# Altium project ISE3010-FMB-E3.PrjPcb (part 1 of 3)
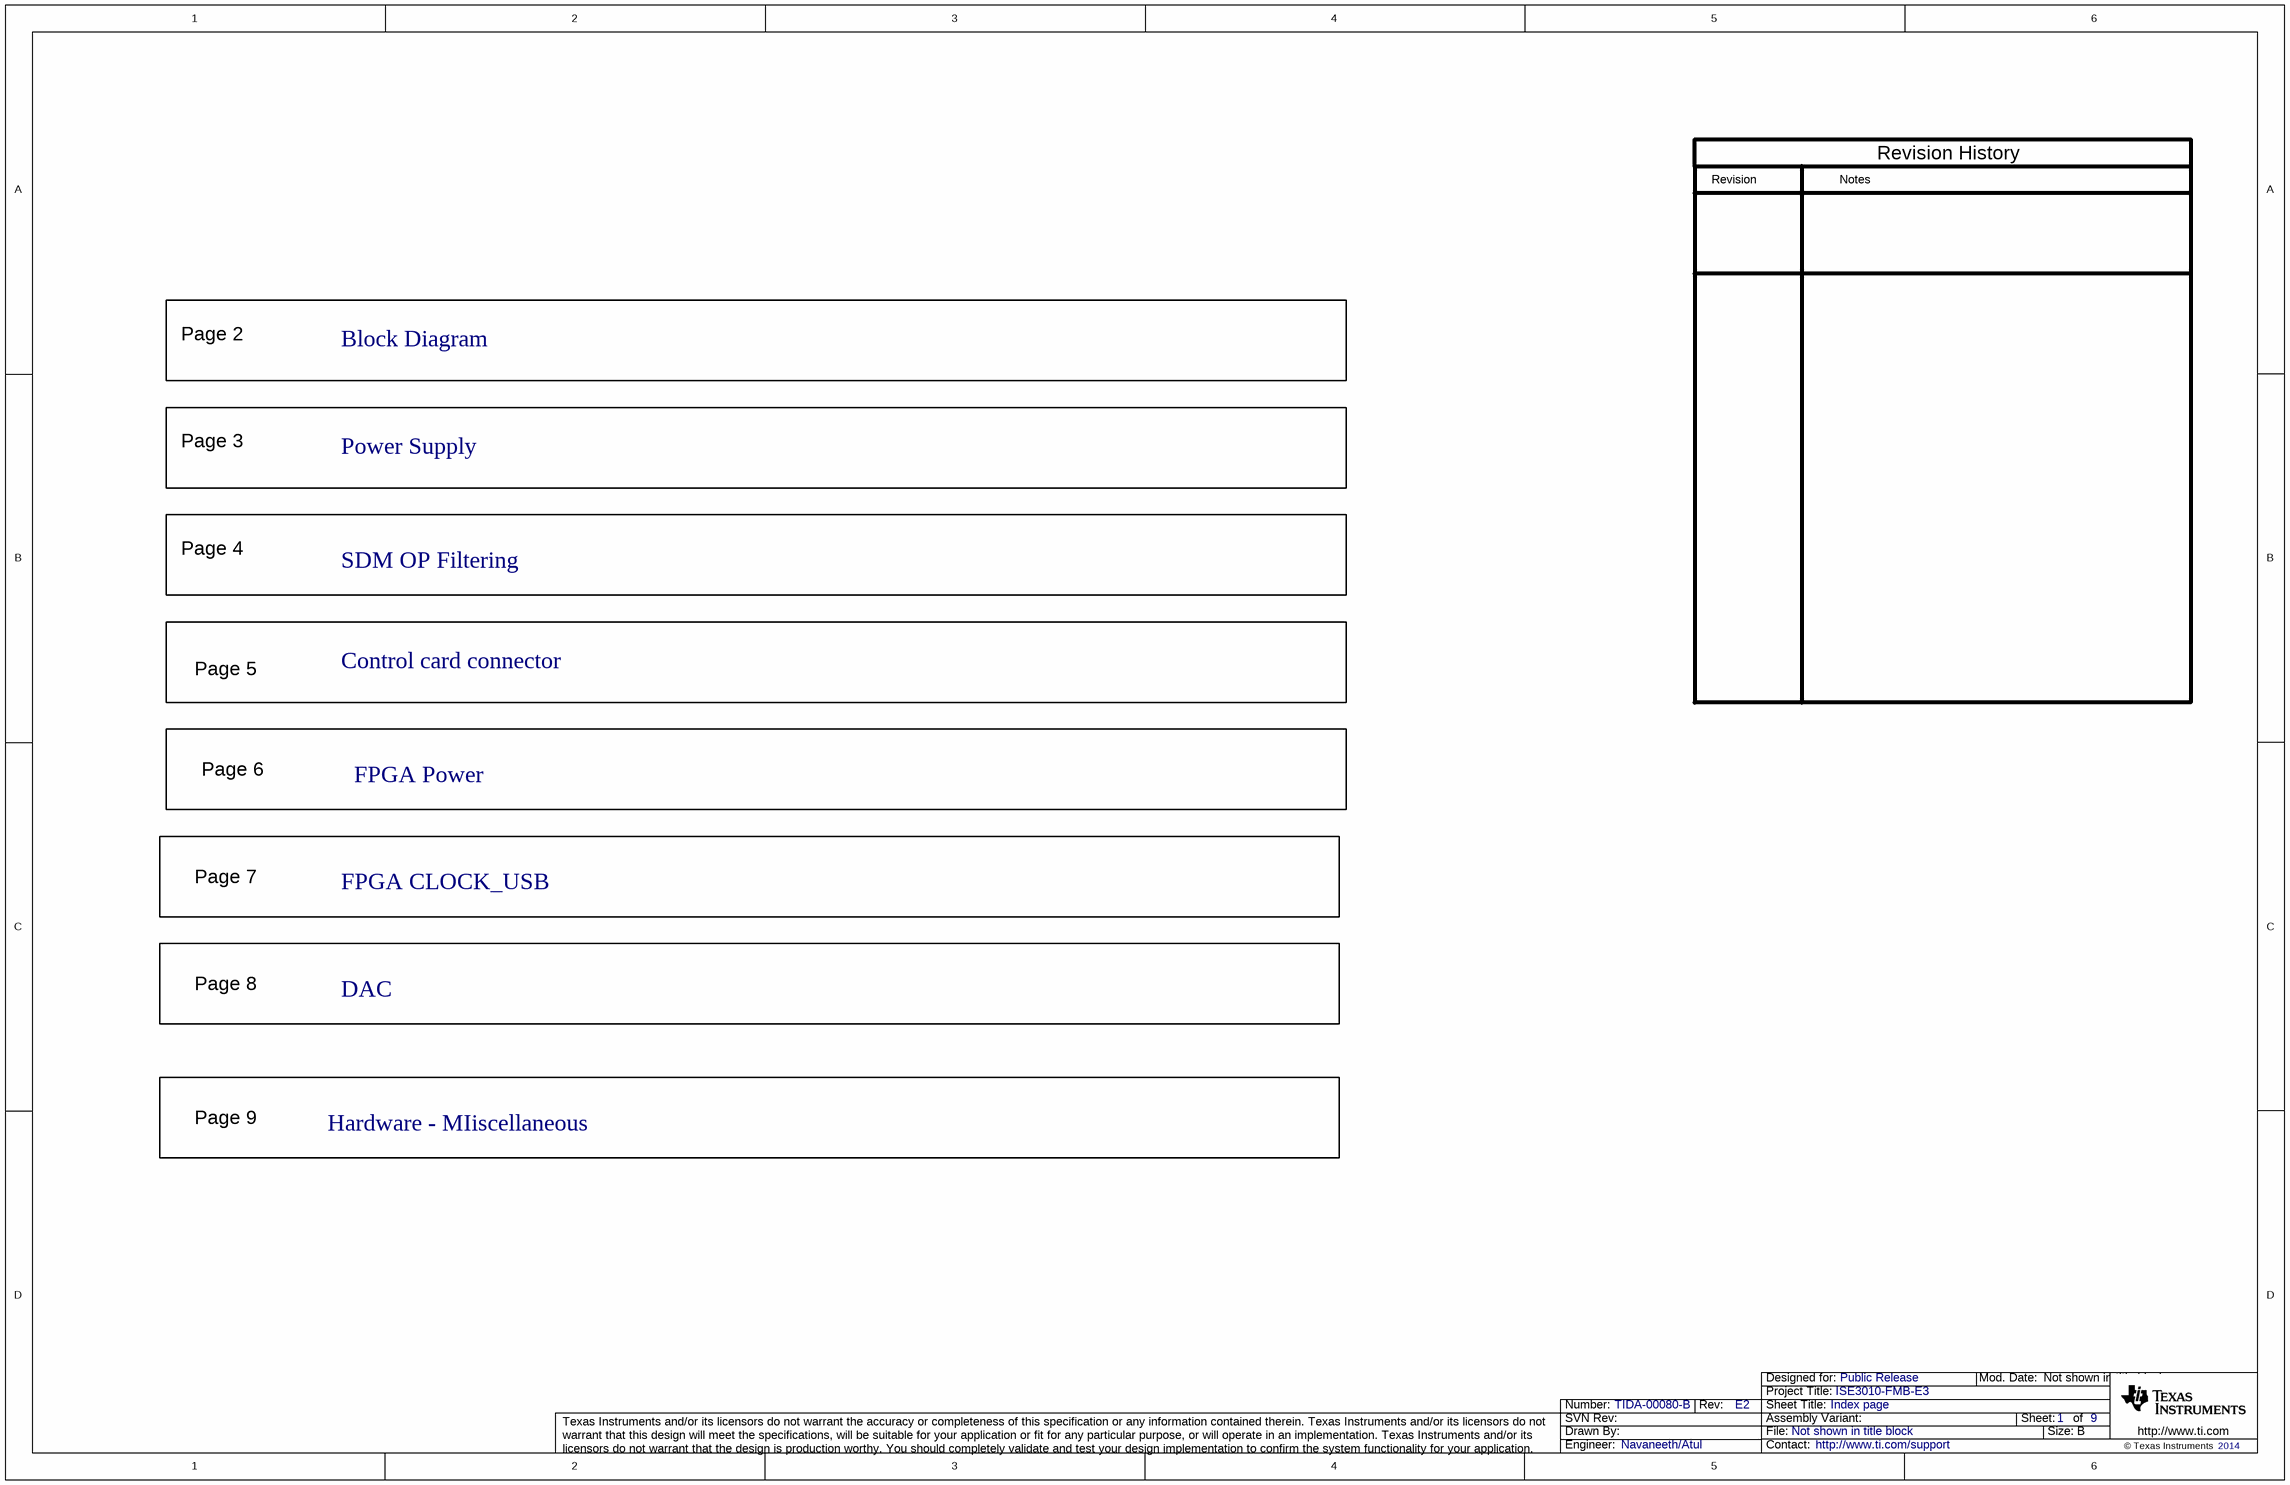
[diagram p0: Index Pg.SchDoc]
CopyrightYear: 2014; PCB_Rev: E2; PRJ_Customer: Public Release; PRJ_Engineer: Navaneeth/Atul; PRJ_Number: TIDA-00080-B; PRJ_Title: ISE3010-FMB-E3; SCH_Rev: E2; TechSupport: http://www.ti.com/support
9 sheets, 508 parts. Net scope: flat (ports and power ports of the same name join across sheets).
Board file: ISE3010-FMB-E3.PcbDoc
Sheets:
  Index Pg.SchDoc
  Block Diagram.SchDoc
  Power Supply.SchDoc
  SDM OP Filtering.SchDoc
  Control card connector.SchDoc
  FPGA Power.SchDoc
  FPGA CLOCK_USB.SchDoc
  DAC.SchDoc
  Hardware.SchDoc

## Sheet Index Pg.SchDoc: Index page
size 431 x 279 mm; Date: Not shown in title block; ApprovedBy: Not shown in title block; CheckedBy: Not shown in title block; Author: Not shown in title block; CompanyName: Not shown in title block; Engineer: Not shown in title block; Organization: Not shown in title block; Address1: Not shown in title block; Address2: Not shown in title block; Address3: Not shown in title block; Address4: Not shown in title block; DocumentNumber: 1; Revision: Use project parameter SCH_Rev; SheetNumber: 1; SheetTotal: 9; PageSetup: Record=PageOptions|CenterHorizontal=True|CenterVertical=True|PrintScale=0.64|XCorrection=1.00|YCorrection=1.00|PrintKind=0|BorderSize=5000000|LeftOffset=0|BottomOffset=0|Orientation=2|PaperLength=1000|PaperWidth=1000|Scale=100|PaperSource=15|PrintQuality=600|MediaType=1|DitherType=10|PaperKind=Letter|PrintScaleMode=1

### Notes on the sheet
- Revision History
- Revision
- Notes
- Page 2
- Block Diagram
- Page 3
- Power Supply
- Page 4
- SDM OP Filtering
- Page 5
- Control card connector
- Page 6
- FPGA Power
- Page 7
- FPGA CLOCK_USB
- Page 8
- DAC
- Page 9
- Hardware - MIiscellaneous

## Sheet Block Diagram.SchDoc: Block Diagram
size 431 x 279 mm; Date: Not shown in title block; ApprovedBy: Not shown in title block; CheckedBy: Not shown in title block; Author: Not shown in title block; CompanyName: Not shown in title block; Engineer: Not shown in title block; Organization: Not shown in title block; Address1: Not shown in title block; Address2: Not shown in title block; Address3: Not shown in title block; Address4: Not shown in title block; DocumentNumber: 2; Revision: Use project parameter SCH_Rev; SheetNumber: 2; SheetTotal: 9; PageSetup: Record=PageOptions|CenterHorizontal=True|CenterVertical=True|PrintScale=1.00|XCorrection=1.00|YCorrection=1.00|PrintKind=0|BorderSize=5000000|LeftOffset=0|BottomOffset=0|Orientation=2|PaperLength=1000|PaperWidth=1000|Scale=100|PaperSource=15|PrintQuality=600|MediaType=1|DitherType=10|PaperKind=Letter|PrintScaleMode=1
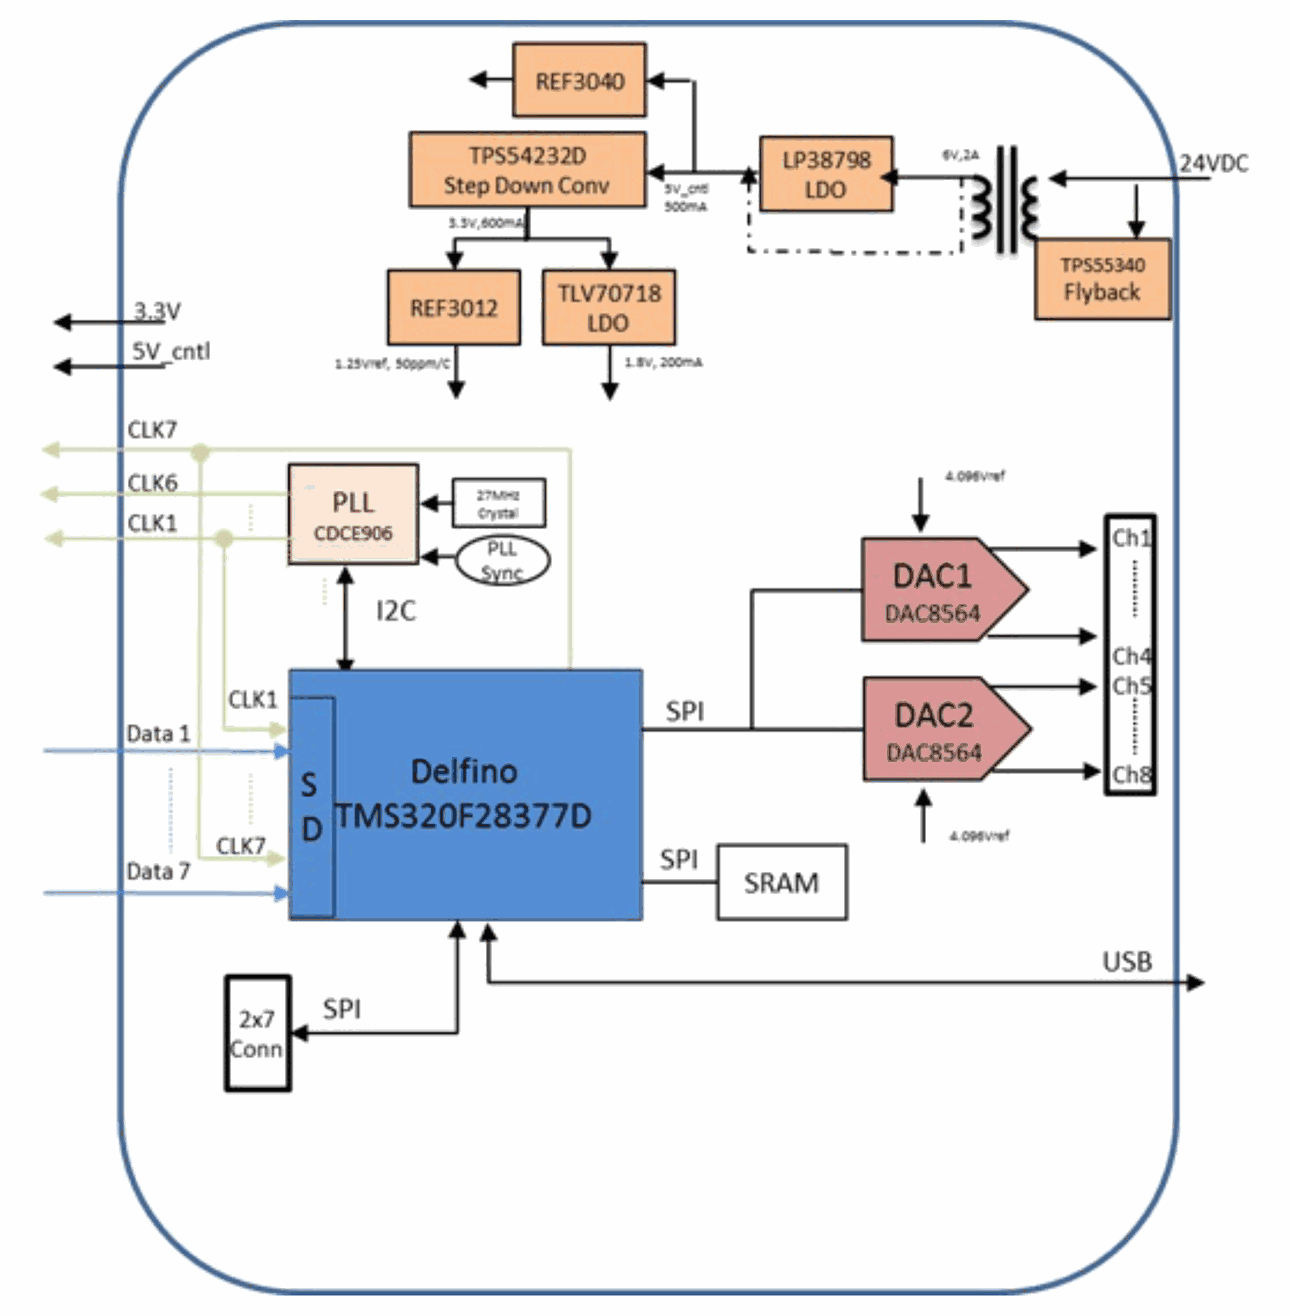
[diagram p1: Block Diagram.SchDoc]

## Sheet Power Supply.SchDoc: Power Supply
size 431 x 279 mm; Date: Not shown in title block; ApprovedBy: Not shown in title block; CheckedBy: Not shown in title block; Author: Not shown in title block; CompanyName: Not shown in title block; Engineer: Not shown in title block; Organization: Not shown in title block; Address1: Not shown in title block; Address2: Not shown in title block; Address3: Not shown in title block; Address4: Not shown in title block; DocumentNumber: 3; Revision: Use project parameter SCH_Rev; SheetNumber: 3; SheetTotal: 9; PageSetup: Record=PageOptions|CenterHorizontal=True|CenterVertical=True|PrintScale=1.00|XCorrection=1.00|YCorrection=1.00|PrintKind=0|BorderSize=5000000|LeftOffset=0|BottomOffset=0|Orientation=2|PaperLength=1000|PaperWidth=1000|Scale=100|PaperSource=15|PrintQuality=600|MediaType=1|DitherType=10|PaperKind=Letter|PrintScaleMode=1
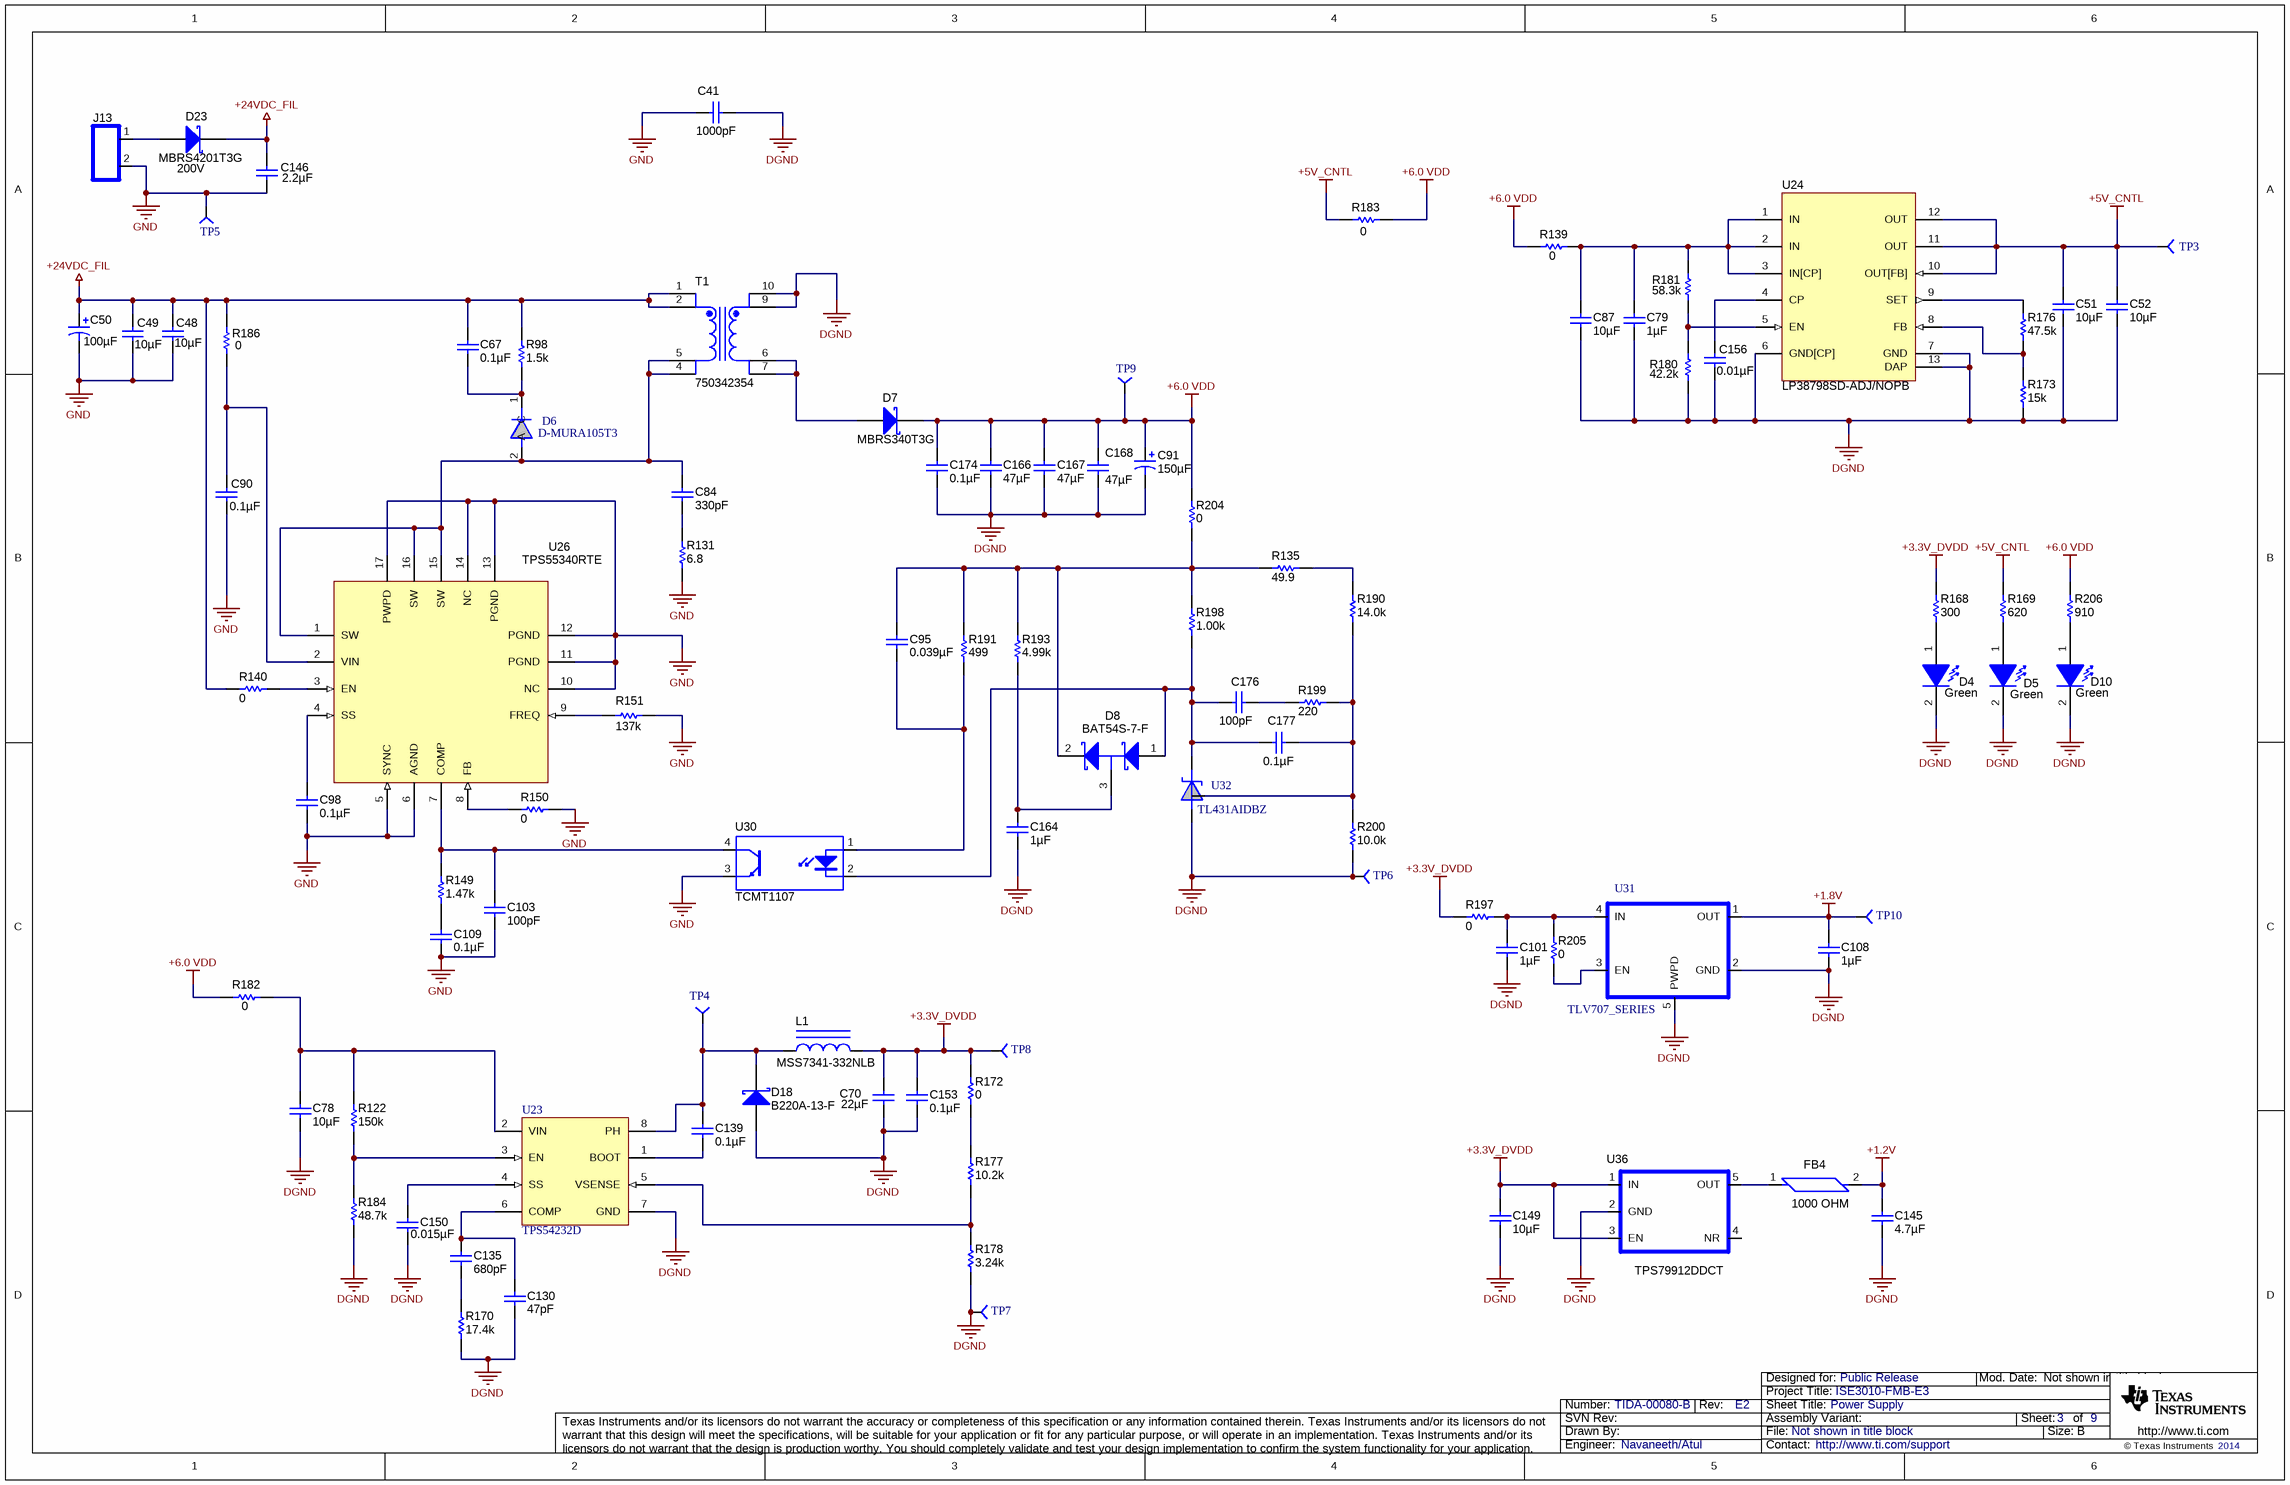
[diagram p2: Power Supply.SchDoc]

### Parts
C41  value 1000pF  [1206]
C48  ValueDisplayed: 10µF  [1210]  (hidden comment: GRM32ER71H106KA12L)
C49  ValueDisplayed: 10µF  [1210]  (hidden comment: GRM32ER71H106KA12L)
C50  ValueDisplayed: 100µF  [HE_800x1150]  (hidden comment: UHE1H101MPD)
C51  ValueDisplayed: 10µF  [1206]  (hidden comment: GRM31CR71C106KAC7L)
C52  ValueDisplayed: 10µF  [1206]  (hidden comment: GRM31CR71C106KAC7L)
C67  ValueDisplayed: 0.1µF  [0603]  (hidden comment: C0603C104K5RACTU)
C70  ValueDisplayed: 22µF  [1210]  (hidden comment: C3225X5R1A226M)
C78  ValueDisplayed: 10µF  [1206]  (hidden comment: GMK316AB7106KL)
C79  ValueDisplayed: 1µF  [1206]  (hidden comment: 12063C105KAT2A)
C84  ValueDisplayed: 330pF  [0603]  (hidden comment: 06035A331JAT2A)
C87  ValueDisplayed: 10µF  [1206]  (hidden comment: GRM31CR71C106KAC7L)
C90  ValueDisplayed: 0.1µF  [0603]  (hidden comment: C0603C104K5RACTU)
C91  ValueDisplayed: 150µF  [SM_RADIAL_6.3BMM]  (hidden comment: UUD1C151MCL1GS)
C95  ValueDisplayed: 0.039µF  [0603]  (hidden comment: GRM188R71H393KA61D)
C98  ValueDisplayed: 0.1µF  [0603]  (hidden comment: 06035C104KAT2A)
C101  ValueDisplayed: 1µF  [0603]  (hidden comment: GRM188R71A105KA61D)
C103  ValueDisplayed: 100pF  [0603]  (hidden comment: C1608C0G1H101J)
C108  ValueDisplayed: 1µF  [0603]  (hidden comment: GRM188R71A105KA61D)
C109  ValueDisplayed: 0.1µF  [0603]  (hidden comment: C0603C104K5RACTU)
C130  ValueDisplayed: 47pF  [0402]  (hidden comment: GRM1555C1E470JA01D)
C135  ValueDisplayed: 680pF  [0603]  (hidden comment: GRM1885C1E681JA01D)
C139  ValueDisplayed: 0.1µF  [0603]  (hidden comment: 0603YC104JAT2A)
C145  ValueDisplayed: 4.7µF  [0603]  (hidden comment: C0603C475K9PACTU)
C146  ValueDisplayed: 2.2µF  [1210]
C149  ValueDisplayed: 10µF  [1210]
C150  ValueDisplayed: 0.015µF  [0603]  (hidden comment: GRM188R71C153KA01D)
C153  ValueDisplayed: 0.1µF  [0603]  (hidden comment: C0603X104K8RACTU)
C156  ValueDisplayed: 0.01µF  [0805_HV]  (hidden comment: 08055C103KAT2A)
C164  ValueDisplayed: 1µF  [0603]  (hidden comment: C0603C105K4PACTU)
C166  ValueDisplayed: 47µF  [1210]  (hidden comment: GRM32ER61A476KE20L)
C167  ValueDisplayed: 47µF  [1210]  (hidden comment: GRM32ER61A476KE20L)
C168  ValueDisplayed: 47µF  [1210]  (hidden comment: GRM32ER61A476KE20L)
C174  ValueDisplayed: 0.1µF  [0603]  (hidden comment: C0603X104K8RACTU)
C176  ValueDisplayed: 100pF  [0603]  (hidden comment: C1608C0G1H101J)
C177  ValueDisplayed: 0.1µF  [0603]  (hidden comment: C0603C104K5RACTU)
D4  value Green  [LED_0603]  (hidden comment: LG L29K-G2J1-24-Z)
D5  value Green  [LED_0603]  (hidden comment: LG L29K-G2J1-24-Z)
D6  D-MURA105T3  [403D]
D7  MBRS340T3G  [SMC]
D8  BAT54S-7-F  [SOT-23]
D10  value Green  [LED_0603]  (hidden comment: LG L29K-G2J1-24-Z)
D18  B220A-13-F  [SMA]
D23  value 200V  [SMC]  (hidden comment: MBRS4201T3G)
FB4  value 1000 OHM  [FB0603]
J13  TBLK_15A_2X5.1MM  [TB_2X5.1MM]  (value not drawn)
L1  MSS7341-332NLB  [MSS7341]
R98  value 1.5k  [1206]  (hidden comment: CRCW12061K50JNEA)
R122  value 150k  [0603]  (hidden comment: RC0603FR-07150KL)
R131  value 6.8  [1206]  (hidden comment: CRCW12066R80JNEA)
R135  value 49.9  [0603]  (hidden comment: CRCW060349R9FKEA)
R139  value 0  [0603]  (hidden comment: CRCW06030000Z0EA)
R140  value 0  [0603]  (hidden comment: CRCW06030000Z0EA)
R149  value 1.47k  [0603]  (hidden comment: RC0603FR-071K47L)
R150  value 0  [0603]  (hidden comment: CRCW06030000Z0EA)
R151  value 137k  [0603]  (hidden comment: CRCW0603137KFKEA)
R168  value 300  [0603]  (hidden comment: CRCW0603300RJNEA)
R169  value 620  [0603]  (hidden comment: RC0603FR-07620RL)
R170  value 17.4k  [0603]  (hidden comment: CRCW060317K4FKEA)
R172  value 0  [0603]  (hidden comment: RC0603JR-070RL)
R173  value 15k  [0603]  (hidden comment: CRCW060315K0JNEA)
R176  value 47.5k  [0603]  (hidden comment: CRCW060347K5FKEA)
R177  value 10.2k  [0603]  (hidden comment: CRCW060310K2FKEA)
R178  value 3.24k  [0603]  (hidden comment: CRCW06033K24FKEA)
R180  value 42.2k  [0603]  (hidden comment: RC0603FR-0742K2L)
R181  value 58.3k  [0603]  (hidden comment: RT0603BRD0758K3L)
R182  value 0  [1206]  (hidden comment: CRCW12060000Z0EA)
R183  value 0  [1206]  (hidden comment: CRCW12060000Z0EA)
R184  value 48.7k  [0603]  (hidden comment: CRCW060348K7FKEA)
R186  value 0  [0603]  (hidden comment: CRCW06030000Z0EA)
R190  value 14.0k  [0603]  (hidden comment: CRCW060314K0FKEA)
R191  value 499  [0603]  (hidden comment: CRCW0603499RFKEA)
R193  value 4.99k  [0603]  (hidden comment: CRCW06034K99FKEA)
R197  value 0  [0603]  (hidden comment: RC0603JR-070RL)
R198  value 1.00k  [0603]  (hidden comment: CRCW06031K00FKEA)
R199  value 220  [0603]  (hidden comment: RC0603FR-07220RL)
R200  value 10.0k  [0603]  (hidden comment: CRCW060310K0FKEA)
R204  value 0  [0603]  (hidden comment: CRCW06030000Z0EA)
R205  value 0  [0603]  (hidden comment: RC0603JR-070RL)
R206  value 910  [0603]  (hidden comment: RG1608P-911-B-T5)
T1  750342354  [XFARMER]
TP3  TP-SMALL  [TP-SMALL]  (value not drawn)
TP4  TP-SMALL  [TP-SMALL]  (value not drawn)
TP5  TP-SMALL  [TP-SMALL]  (value not drawn)
TP6  TP-SMALL  [TP-SMALL]  (value not drawn)
TP7  TP-SMALL  [TP-SMALL]  (value not drawn)
TP8  TP-SMALL  [TP-SMALL]  (value not drawn)
TP9  TP-SMALL  [TP-SMALL]  (value not drawn)
TP10  TP-SMALL  [TP-SMALL]  (value not drawn)
U23  TPS54232D  [D0008A_N]
U24  LP38798SD-ADJ/NOPB  [DNT0012B]
U26  TPS55340RTE  [RTE0016C]
U30  TCMT1107  [SOP-4]
U31  TLV707_SERIES  [UDFN-4P-1X1_MM]
U32  TL431AIDBZ  [SOT-23]
U36  TPS79912DDCT  [DDC0005A_N]

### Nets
+1.2V: C145.1 FB4.2
+1.8V: C108.1 TP10.1 U31.1(OUT)
+3.3V_DVDD: C70.1 C149.1 C153.1 L1.2 R168.2 R172.2 R197.2 TP8.1 U36.1(IN) U36.3(EN)
+5V_CNTL: C51.1 C52.1 R169.2 R183.1 TP3.1 U24.10(OUT[FB]) U24.11(OUT) U24.12(OUT)
+6.0 VDD: C91.1(+) C166.1 C167.1 C168.1 C174.1 D7.1(K) R139.2 R182.1 R183.2 R204.2 R206.2 TP9.1
+24VDC_FIL: C48.1 C49.1 C50.1(+) C67.1 C146.1 D23.1(K) R98.2 R140.2 R186.2 T1.1 T1.2
DGND: C41.2 C51.2 C52.2 C70.2 C78.2 C79.2 C87.2 C91.2(-) C101.2 C108.2 C130.2 C145.2 C149.2 C150.2 C153.2 C156.2 C164.2 C166.2 C167.2 C168.2 C174.2 D4.2(K) D5.2(K) D10.2(K) D18.2(A) R170.1 R173.1 R178.1 R180.1 R184.1 R200.1 T1.9 T1.10 TP6.1 TP7.1 U23.7(GND) U24.6(GND[CP]) U24.7(GND) U24.13(DAP) U31.2(GND) U31.5(PWPD) U32.3(A) U36.2(GND)
GND: C41.1 C48.2 C49.2 C50.2(-) C90.2 C98.2 C103.2 C109.2 C146.2 J13.2 R131.1 R150.2 R151.2 TP5.1 U26.5(SYNC) U26.6(AGND) U26.10(NC) U26.11(PGND) U26.12(PGND) U26.13(PGND) U26.14(NC) U26.17(PWPD) U30.3(E)
NetC67_2: C67.2 D6.1(C) R98.1
NetC78_1: C78.1 R122.2 R182.2 U23.2(VIN)
NetC79_1: C79.1 C87.1 R139.1 R181.2 U24.1(IN) U24.2(IN) U24.3(IN[CP])
NetC84_1: C84.1 D6.2(A) T1.4 T1.5 U26.1(SW) U26.15(SW) U26.16(SW)
NetC84_2: C84.2 R131.2
NetC90_1: C90.1 R186.1 U26.2(VIN)
NetC95_1: C95.1 D8.2(K) R135.1 R191.2 R193.2 R198.2 R204.1
NetC95_2: C95.2 R191.1 U30.1(A)
NetC98_1: C98.1 U26.4(SS)
NetC101_1: C101.1 R197.1 R205.2 U31.4(IN)
NetC103_1: C103.1 R149.2 U26.7(COMP) U30.4(C)
NetC109_1: C109.1 R149.1
NetC130_1: C130.1 C135.1 U23.6(COMP)
NetC135_2: C135.2 R170.2
NetC139_1: C139.1 D18.1(K) L1.1 TP4.1 U23.8(PH)
NetC139_2: C139.2 U23.1(BOOT)
NetC150_1: C150.1 U23.4(SS)
NetC156_1: C156.1 U24.4(CP)
NetC164_1: C164.1 D8.3(C) R193.1
NetC176_1: C176.1 R199.1
NetC176_2: C176.2 C177.1 D8.1(A) R198.1 U30.2(K) U32.1(C)
NetC177_2: C177.2 R190.1 R199.2 R200.2 U32.2(REF)
NetD4_1: D4.1(A) R168.1
NetD5_1: D5.1(A) R169.1
NetD7_2: D7.2(A) T1.6 T1.7
NetD10_1: D10.1(A) R206.1
NetD23_2: D23.2(A) J13.1
NetFB4_1: FB4.1 U36.5(OUT)
NetR122_1: R122.1 R184.2 U23.3(EN)
NetR135_2: R135.2 R190.2
NetR140_1: R140.1 U26.3(EN)
NetR150_1: R150.1 U26.8(FB)
NetR151_1: R151.1 U26.9(FREQ)
NetR172_1: R172.1 R177.2
NetR173_2: R173.2 R176.1 U24.8(FB)
NetR176_2: R176.2 U24.9(SET)
NetR177_1: R177.1 R178.2 U23.5(VSENSE)
NetR180_2: R180.2 R181.1 U24.5(EN)
NetR205_1: R205.1 U31.3(EN)

Not connected (* = marked no-connect by the designer): U36 4(NR)

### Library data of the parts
C41 = 202R18W102KV4E: CAP, CERM, 1000pF, 2KV 10% X7R 1206; Manufacturer: Johanson Dielectrics Inc; Polarized: N; CompType: Capacitor; Cap_F: 0.000000001; Tolerance_%: 0
C48 C49 = GRM32ER71H106KA12L: CAP, CERM, 10uF, 50V, +/-10%, X7R, 1210; Manufacturer: MuRata; Polarized: N; CompType: Capacitor; U/M: EA; Cap_F: 0.00001; Tolerance_%: 10; Value1: Unknown; VDC_V: 50; TaMin_C: -55; TaMax_C: 125
C50 = UHE1H101MPD: CAP, AL, 100uF, 50V, +/-20%, 0.17 ohm, TH; Manufacturer: Nichicon; Polarized: Y; CompType: Capacitor; U/M: EA; Cap_F: 0.0001; Tolerance_%: 20; VDC_V: 50; ESR_Ohm: 0.17; IRMS_A: 0.555; TaMin_C: -40; TaMax_C: 105; Cap_Case: 8x11.5
C51 C52 C87 = GRM31CR71C106KAC7L: CAP, CERM, 10uF, 16V, +/-10%, X7R, 1206; Manufacturer: MuRata; Polarized: N; CompType: Capacitor; U/M: EA; Cap_F: 0.00001; Tolerance_%: 10; Value1: Unknown; VDC_V: 16; TaMin_C: -55; TaMax_C: 125
C67 C90 C109 C177 = C0603C104K5RACTU: CAP, CERM, 0.1uF, 50V, +/-10%, X7R, 0603; Manufacturer: Kemet; Polarized: N; CompType: Capacitor; U/M: EA; Cap_F: 0.0000001; Tolerance_%: 10; Value1: Unknown; VDC_V: 50; TaMin_C: -55; TaMax_C: 125
C70 = C3225X5R1A226M: CAP, CERM, 22uF, 10V, +/-20%, X5R, 1210; Manufacturer: TDK; Polarized: N; CompType: Capacitor; U/M: EA; Cap_F: 0.000022; Tolerance_%: 20; ESR_Ohm: 0.002; Value1: 0.002 ohm; VDC_V: 10; IRMS_A: 3.2; TaMin_C: -55; TaMax_C: 85
C78 = GMK316AB7106KL: CAP, CERM, 10uF, 35V, +/-10%, X7R, 1206; Manufacturer: Taiyo Yuden; Polarized: N; CompType: Capacitor; U/M: EA; Cap_F: 0.00001; Tolerance_%: 10; Value1: Unknown; VDC_V: 35; TaMin_C: -55; TaMax_C: 125
C79 = 12063C105KAT2A: CAP, CERM, 1uF, 25V, +/-10%, X7R, 1206; Manufacturer: AVX; Polarized: N; CompType: Capacitor; U/M: EA; Cap_F: 0.000001; Tolerance_%: 10; ESR_Ohm: 0.013; Value1: 0.013 ohm; VDC_V: 25; TaMin_C: -55; TaMax_C: 125
C84 = 06035A331JAT2A: CAP, CERM, 330pF, 50V, +/-5%, C0G/NP0, 0603; Manufacturer: AVX; Polarized: N; CompType: Capacitor; U/M: EA; Cap_F: 0.00000000033; Tolerance_%: 5; ESR_Ohm: 0.071; Value1: 0.071 ohm; VDC_V: 50; TaMin_C: -55; TaMax_C: 125
C91 = UUD1C151MCL1GS: CAP, AL, 150uF, 16V, +/-20%, 0.34 ohm, SMD; Manufacturer: Nichicon; Polarized: Y; CompType: Capacitor; U/M: EA; Cap_F: 0.00015; Tolerance_%: 20; VDC_V: 16; ESR_Ohm: 0.34; IRMS_A: 0.28; TaMin_C: -55; TaMax_C: 105; Cap_Case: 6.3x7.7
C95 = GRM188R71H393KA61D: CAP, CERM, 0.039uF, 50V, +/-10%, X7R, 0603; Manufacturer: MuRata; Polarized: N; CompType: Capacitor; U/M: EA; Cap_F: 0.000000039; Tolerance_%: 10; Value1: Unknown; VDC_V: 50; TaMin_C: -55; TaMax_C: 125
C98 = 06035C104KAT2A: CAP, CERM, 0.1uF, 50V, +/-10%, X7R, 0603; Manufacturer: AVX; Polarized: N; CompType: Capacitor; U/M: EA; Cap_F: 0.0000001; Tolerance_%: 10; Value1: Unknown; VDC_V: 50; TaMin_C: -55; TaMax_C: 125
C101 C108 = GRM188R71A105KA61D: CAP, CERM, 1uF, 10V, +/-10%, X7R, 0603; Manufacturer: MuRata; Polarized: N; CompType: Capacitor; U/M: EA; Cap_F: 0.000001; Tolerance_%: 10; ESR_Ohm: 0.011; Value1: 0.011 ohm; TaMin_C: -55; TaMax_C: 125
C103 C176 = C1608C0G1H101J: CAP, CERM, 100pF, 50V, +/-5%, C0G/NP0, 0603; Manufacturer: TDK; Polarized: N; CompType: Capacitor; U/M: EA; Cap_F: 0.0000000001; Tolerance_%: 5; ESR_Ohm: 0.1679; Value1: 0.1679 ohm; VDC_V: 50; TaMin_C: -55; TaMax_C: 125
C130 = GRM1555C1E470JA01D: CAP, CERM, 47pF, 25V, +/-5%, C0G/NP0, 0402; Manufacturer: MuRata; Polarized: N; CompType: Capacitor; U/M: EA; Cap_F: 0.000000000047; Tolerance_%: 5; Value1: Unknown; VDC_V: 25; TaMin_C: -55; TaMax_C: 125
C135 = GRM1885C1E681JA01D: CAP, CERM, 680pF, 25V, +/-5%, C0G/NP0, 0603; Manufacturer: MuRata; Polarized: N; CompType: Capacitor; U/M: EA; Cap_F: 0.00000000068; Tolerance_%: 5; Value1: Unknown; VDC_V: 25; TaMin_C: -55; TaMax_C: 125
C139 = 0603YC104JAT2A: CAP, CERM, 0.1uF, 16V, +/-5%, X7R, 0603; Manufacturer: AVX; Polarized: N; CompType: Capacitor; U/M: EA; Cap_F: 0.0000001; Tolerance_%: 5; ESR_Ohm: 0.039; Value1: 0.039 ohm; VDC_V: 16; TaMin_C: -55; TaMax_C: 125
C145 = C0603C475K9PACTU: CAP, CERM, 4.7uF, 6.3V, +/-10%, X5R, 0603; Manufacturer: Kemet; Polarized: N; CompType: Capacitor; U/M: EA; Cap_F: 0.0000047; Tolerance_%: 10; ESR_Ohm: 0.006; Value1: 0.006 ohm; VDC_V: 6.3; IRMS_A: 7.24; TaMin_C: -55; TaMax_C: 85
C146 = GRM32ER72A225KA35L: CAP, CERM, 2.2uF, 100V, +/-10%, X7R, 1210; Manufacturer: MuRata; Polarized: N; CompType: Capacitor; U/M: EA; Cap_F: 0.0000022; Tolerance_%: 10; ESR_Ohm: 0.007; Value1: 0.007 ohm; VDC_V: 100; IRMS_A: 4.4; TaMin_C: -55; TaMax_C: 125
C149 = GMK325AB7106MM-T: CAP, CERM, 10uF, 35V, +/-20%, X7R, 1210; Manufacturer: Taiyo Yuden; Polarized: N; CompType: Capacitor; U/M: EA; Cap_F: 0.00001; Tolerance_%: 20; Value1: Unknown; VDC_V: 35; TaMin_C: -55; TaMax_C: 125
C150 = GRM188R71C153KA01D: CAP, CERM, 0.015uF, 16V, +/-10%, X7R, 0603; Manufacturer: MuRata; Polarized: N; CompType: Capacitor; U/M: EA; Cap_F: 0.000000015; Tolerance_%: 10; Value1: Unknown; VDC_V: 16; TaMin_C: -55; TaMax_C: 125
C153 C174 = C0603X104K8RACTU: CAP, CERM, 0.1uF, 10V, +/-10%, X7R, 0603; Manufacturer: Kemet; Polarized: N; CompType: Capacitor; U/M: EA; Cap_F: 0.0000001; Tolerance_%: 10; Value1: Unknown; TaMin_C: -55; TaMax_C: 125
C156 = 08055C103KAT2A: CAP, CERM, 0.01uF, 50V, +/-10%, X7R, 0805; Manufacturer: AVX; Polarized: N; CompType: Capacitor; U/M: EA; Cap_F: 0.00000001; Tolerance_%: 10; ESR_Ohm: 0.078; Value1: 0.078 ohm; VDC_V: 50; TaMin_C: -55; TaMax_C: 125; Cap_Case: 0805
C164 = C0603C105K4PACTU: CAP, CERM, 1uF, 16V, +/-10%, X5R, 0603; Manufacturer: Kemet; Polarized: N; CompType: Capacitor; U/M: EA; Cap_F: 0.000001; Tolerance_%: 10; Value1: Unknown; VDC_V: 16; TaMin_C: -55; TaMax_C: 85
C166-C168 = GRM32ER61A476KE20L: CAP, CERM, 47uF, 10V, +/-10%, X5R, 1210; Manufacturer: MuRata; Polarized: N; CompType: Capacitor; U/M: EA; Cap_F: 0.000047; Tolerance_%: 10; ESR_Ohm: 0.001; Value1: 0.001 ohm; TaMin_C: -55; TaMax_C: 85
D4 D5 D10 = LG M47K-G1J2-24-Z: LED SMARTLED GREEN 570NM 0603; Manufacturer: OSRAM Opto Semiconductors Inc; Vf_V: 1.7V; Io_A: 0.002; RJC_CperW: 530; Tjmax_C: 100; Value1: W; U/M: EA
D6 = D-MURA105T3: Rectifier, Ultrafast Power, 50V 1A; Manufacturer: On Semi; Area: 4088
D7 = MBRS340T3G: Diode, Schottky, 40V, 3A, SMC; Manufacturer: ON Semiconductor; U/M: EA; Vf_V: 0.525; Value2: 0.525V; Io_A: 3; Vr_V: 40; TJmax_C: 125; RJC_CperW: 11
D8 = BAT54S-7-F: Diode, Schottky, 30V, 0.2A, SOT-23; Manufacturer: Diodes Inc.; U/M: EA; Vf_V: 0.65; Value2: 0.65V; Io_A: 0.2; Vr_V: 30; TJmax_C: 125
D18 = B220A-13-F: Diode, Schottky, 20V, 2A, SMA; Manufacturer: Diodes Inc.; U/M: EA; Vf_V: 0.5; Value2: 0.5V; Io_A: 2; Vr_V: 20; TJmax_C: 150
D23 = MBRS4201T3G: Diode, Schottky, 200V, 4A, SMC; Manufacturer: ON Semiconductor; Io_A: 4
FB4 = MMZ1608B102C: FERRITE CHIP 1000 OHM 300MA 0603; Manufacturer: TDK Corporation; CompType: Ferrite Bead
J13 = TBLK_15A_2X5.1MM: Terminal Block, 2-pin, 15-A, 5.1mm; Manufacturer: OST; PartNumber: ED120/2DS; area: 141600; Value: ED120/2DS
L1 = MSS7341-332NLB: Inductor, Shielded Drum Core, Ferrite, 3.3uH, 3.72A, 0.02 ohm, SMD; Manufacturer: Coilcraft; Ind_H: 3.3E-6; ValueDisplayed: 3.3µH; Imax_A: 3.72; Irms: 5A @ 40C rise; Isat: 3.72A @ 30% inductance drop; DCR_ohm: 0.02; U/M: EA
R98 = CRCW12061K50JNEA: RES, 1.5k ohm, 5%, 0.25W, 1206; Manufacturer: Vishay-Dale; CompType: Resistor; Res_ohm: 1500; Value_Code: 1k50; Tolerance_%: 5; Power_W: 0.25; VDC_V: 200; TempCo: 200 ppm/C; EIA_Code: E24; U/M: EA
R122 = RC0603FR-07150KL: RES, 150k ohm, 1%, 0.1W, 0603; Manufacturer: Yageo America; CompType: Resistor; Res_ohm: 150000; Tolerance_%: 1; Power_W: 0.1; VDC_V: 150; TempCo: 200 ppm/C; EIA_Code: E96; U/M: EA
R131 = CRCW12066R80JNEA: RES, 6.8 ohm, 5%, 0.25W, 1206; Manufacturer: Vishay-Dale; CompType: Resistor; Value_Code: 6R80; Tolerance_%: 5; Power_W: 0.25; VDC_V: 200; TempCo: 200 ppm/C; EIA_Code: E24; U/M: EA
R135 = CRCW060349R9FKEA: RES, 49.9 ohm, 1%, 0.1W, 0603; Manufacturer: Vishay-Dale; CompType: Resistor; Value_Code: 49R9; Tolerance_%: 1; Power_W: 0.1; VDC_V: 75; TempCo: 100 ppm/C; EIA_Code: E96; U/M: EA
R139 R140 R150 R186 R204 = CRCW06030000Z0EA: RES, 0 ohm, 5%, 0.1W, 0603; Manufacturer: Vishay-Dale; CompType: Resistor; Value_Code: 0000; Tolerance_%: 5; Power_W: 0.1; VDC_V: 75; TempCo: 200 ppm/C; EIA_Code: E24; U/M: EA
R149 = RC0603FR-071K47L: RES, 1.47k ohm, 1%, 0.1W, 0603; Manufacturer: Yageo America; CompType: Resistor; Res_ohm: 1470; Value_Code: 1k47; Tolerance_%: 1; Power_W: 0.1; VDC_V: 150; TempCo: 200 ppm/C; EIA_Code: E96; U/M: EA
R151 = CRCW0603137KFKEA: RES, 137k ohm, 1%, 0.1W, 0603; Manufacturer: Vishay-Dale; CompType: Resistor; Res_ohm: 137000; Tolerance_%: 1; Power_W: 0.1; VDC_V: 75; TempCo: 100 ppm/C; EIA_Code: E96; U/M: EA
R168 = CRCW0603300RJNEA: RES, 300 ohm, 5%, 0.1W, 0603; Manufacturer: Vishay-Dale; CompType: Resistor; Value_Code: 300R; Tolerance_%: 5; Power_W: 0.1; VDC_V: 75; TempCo: 200 ppm/C; EIA_Code: E24; U/M: EA
R169 = RC0603FR-07620RL: RES, 620 ohm, 1%, 0.1W, 0603; Manufacturer: Yageo America; CompType: Resistor; Value_Code: 620R; Tolerance_%: 1; Power_W: 0.1; VDC_V: 150; TempCo: 200 ppm/C; U/M: EA
R170 = CRCW060317K4FKEA: RES, 17.4k ohm, 1%, 0.1W, 0603; Manufacturer: Vishay-Dale; CompType: Resistor; Res_ohm: 17400; Value_Code: 17k4; Tolerance_%: 1; Power_W: 0.1; VDC_V: 75; TempCo: 100 ppm/C; EIA_Code: E96; U/M: EA
R172 R197 R205 = RC0603JR-070RL: RES, 0 ohm, 5%, 0.1W, 0603; Manufacturer: Yageo America; CompType: Resistor; Value_Code: 0000; Tolerance_%: 5; Power_W: 0.1; VDC_V: 50; TempCo: 200 ppm/C; EIA_Code: E24; U/M: EA
R173 = CRCW060315K0JNEA: RES, 15k ohm, 5%, 0.1W, 0603; Manufacturer: Vishay-Dale; CompType: Resistor; Res_ohm: 15000; Value_Code: 15k0; Tolerance_%: 5; Power_W: 0.1; VDC_V: 75; TempCo: 200 ppm/C; EIA_Code: E24; U/M: EA
R176 = CRCW060347K5FKEA: RES, 47.5k ohm, 1%, 0.1W, 0603; Manufacturer: Vishay-Dale; CompType: Resistor; Res_ohm: 47500; Value_Code: 47k5; Tolerance_%: 1; Power_W: 0.1; VDC_V: 75; TempCo: 100 ppm/C; EIA_Code: E96; U/M: EA
R177 = CRCW060310K2FKEA: RES, 10.2k ohm, 1%, 0.1W, 0603; Manufacturer: Vishay-Dale; CompType: Resistor; Res_ohm: 10200; Value_Code: 10k2; Tolerance_%: 1; Power_W: 0.1; VDC_V: 75; TempCo: 100 ppm/C; EIA_Code: E96; U/M: EA
R178 = CRCW06033K24FKEA: RES, 3.24k ohm, 1%, 0.1W, 0603; Manufacturer: Vishay-Dale; CompType: Resistor; Res_ohm: 3240; Value_Code: 3k24; Tolerance_%: 1; Power_W: 0.1; VDC_V: 75; TempCo: 100 ppm/C; EIA_Code: E96; U/M: EA
R180 = RC0603FR-0742K2L: RES, 42.2k ohm, 1%, 0.1W, 0603; Manufacturer: Yageo America; CompType: Resistor; Res_ohm: 42200; Value_Code: 42k2; Tolerance_%: 1; Power_W: 0.1; VDC_V: 150; TempCo: 200 ppm/C; EIA_Code: E96; U/M: EA
R181 = RT0603BRD0758K3L: RES, 58.3k ohm, 0.1%, 0.1W, 0603; Manufacturer: Yageo America; CompType: Resistor; Res_ohm: 58300; Value_Code: 58k3; Tolerance_%: 0.1; VDC_V: 75; TempCo: 25 ppm/C; EIA_Code: E192; U/M: EA
R182 R183 = CRCW12060000Z0EA: RES, 0 ohm, 5%, 0.25W, 1206; Manufacturer: Vishay-Dale; CompType: Resistor; Value_Code: 0000; Tolerance_%: 5; Power_W: 0.25; VDC_V: 200; TempCo: 200 ppm/C; EIA_Code: E24; U/M: EA
R184 = CRCW060348K7FKEA: RES, 48.7k ohm, 1%, 0.1W, 0603; Manufacturer: Vishay-Dale; CompType: Resistor; Res_ohm: 48700; Value_Code: 48k7; Tolerance_%: 1; Power_W: 0.1; VDC_V: 75; TempCo: 100 ppm/C; EIA_Code: E96; U/M: EA
R190 = CRCW060314K0FKEA: RES, 14.0k ohm, 1%, 0.1W, 0603; Manufacturer: Vishay-Dale; CompType: Resistor; Res_ohm: 14000; Value_Code: 14k0; Tolerance_%: 1; Power_W: 0.1; VDC_V: 75; TempCo: 100 ppm/C; EIA_Code: E96; U/M: EA
R191 = CRCW0603499RFKEA: RES, 499 ohm, 1%, 0.1W, 0603; Manufacturer: Vishay-Dale; CompType: Resistor; Value_Code: 499R; Tolerance_%: 1; Power_W: 0.1; VDC_V: 75; TempCo: 100 ppm/C; EIA_Code: E96; U/M: EA
R193 = CRCW06034K99FKEA: RES, 4.99k ohm, 1%, 0.1W, 0603; Manufacturer: Vishay-Dale; CompType: Resistor; Res_ohm: 4990; Value_Code: 4k99; Tolerance_%: 1; Power_W: 0.1; VDC_V: 75; TempCo: 100 ppm/C; EIA_Code: E96; U/M: EA
R198 = CRCW06031K00FKEA: RES, 1.00k ohm, 1%, 0.1W, 0603; Manufacturer: Vishay-Dale; CompType: Resistor; Res_ohm: 1000; Value_Code: 1k00; Tolerance_%: 1; Power_W: 0.1; VDC_V: 75; TempCo: 100 ppm/C; EIA_Code: E96; U/M: EA
R199 = RC0603FR-07220RL: RES, 220 ohm, 1%, 0.1W, 0603; Manufacturer: Yageo America; CompType: Resistor; Value_Code: 220R; Tolerance_%: 1; Power_W: 0.1; VDC_V: 150; TempCo: 200 ppm/C; U/M: EA
R200 = CRCW060310K0FKEA: RES, 10.0k ohm, 1%, 0.1W, 0603; Manufacturer: Vishay-Dale; CompType: Resistor; Res_ohm: 10000; Value_Code: 10k0; Tolerance_%: 1; Power_W: 0.1; VDC_V: 75; TempCo: 100 ppm/C; EIA_Code: E96; U/M: EA
R206 = RG1608P-911-B-T5: RES, 910 ohm, 0.1%, 0.1W, 0603; Manufacturer: Susumu Co Ltd; CompType: Resistor; Value_Code: 910R; Tolerance_%: 0.1; VDC_V: 75; TempCo: 25 ppm/C; U/M: EA
T1 = Transformer: Manufacturer: Wurth; SymbolCreator: a0411947; DCR_Ohm: 0.11; Value: 12uH; LeakageL: 0.130uH; U/M: EA
TP3-TP10 = TP-SMALL: Test Point, 0.020 Hole; Manufacturer: STD; Value: STD
U23 = TPS54232D: Buck Step Down Regulator with 3.5 to 28 V Input and 0.8 to 25 V Output, -40 to 150 degC, 8-Pin SOIC (D), Green (RoHS & no Sb/Br); Manufacturer: Texas Instruments; Alternate Manufacturer: None; Alternate PartNumber: Equivalent; Duty Cycle(Max)(%): 90; Iout(Max)(A): 2; Iq(Typ)(mA): 0.11; Rating: Catalog; Regulated Outputs(#): 1; SubFamily: Step-Down Regulator; Switch Current Limit(Typ)(A): 2.3; Vin(Max)(V): 28; Vin(Min)(V): 3.5; Vout(Max)(V): 25; Vout(Min)(V): 0.8
U24 = LP38798SD-ADJ/NOPB: Ultra Low Noise, 800 mA Linear Voltage Regulator for RF/Analog Circuits, DNT0012B; Alternate Manufacturer: None; Manufacturer: Texas Instruments; SymbolCreator: a0799628; CompType: IC; U/M: EA
U26 = TPS55340RTE: Integrated 5-A 40-V Wide Input Range Boost/SEPIC/Flyback DC-DC Regulator, RTE0016C; Alternate Manufacturer: None; Manufacturer: Texas Instruments; SymbolCreator: a0412235; CompType: IC; U/M: EA
U30 = TCMT1107: Optocoupler, 3.75kV RMS, SMT; Manufacturer: Vishay-Semiconductor; U/M: EA
U31 = TLV707_SERIES: IC, 150mA, Low IQ, LDO Regulator; PartNumber: TLV707xxx; Manufacturer: TI; Alternate Manufacturer: None; Area: 2.25 mm; Value: TLV707xxx
U32 = TL431AIDBZ: IC, Precision Adjustable Shunt Regulator; Manufacturer: TI; Alternate Manufacturer: None; Area: 16384; Value: TL431DBZ
U36 = TPS799XXDDC: IC, Ultra-low Noise, High PSRR 200 mA, LDO, 1.2V 0.2A 5SOT; Manufacturer: TI; Alternate Manufacturer: None; Area: 23200

## Sheet SDM OP Filtering.SchDoc: SDM OP Filtering
size 431 x 279 mm; Date: Not shown in title block; ApprovedBy: Not shown in title block; CheckedBy: Not shown in title block; Author: Not shown in title block; CompanyName: Not shown in title block; Engineer: Not shown in title block; Organization: Not shown in title block; Address1: Not shown in title block; Address2: Not shown in title block; Address3: Not shown in title block; Address4: Not shown in title block; DocumentNumber: 4; Revision: Use project parameter SCH_Rev; SheetNumber: 4; SheetTotal: 9; PageSetup: Record=PageOptions|CenterHorizontal=True|CenterVertical=True|PrintScale=1.00|XCorrection=1.00|YCorrection=1.00|PrintKind=0|BorderSize=5000000|LeftOffset=0|BottomOffset=0|Orientation=2|PaperLength=1000|PaperWidth=1000|Scale=100|PaperSource=15|PrintQuality=600|MediaType=1|DitherType=10|PaperKind=Letter|PrintScaleMode=1
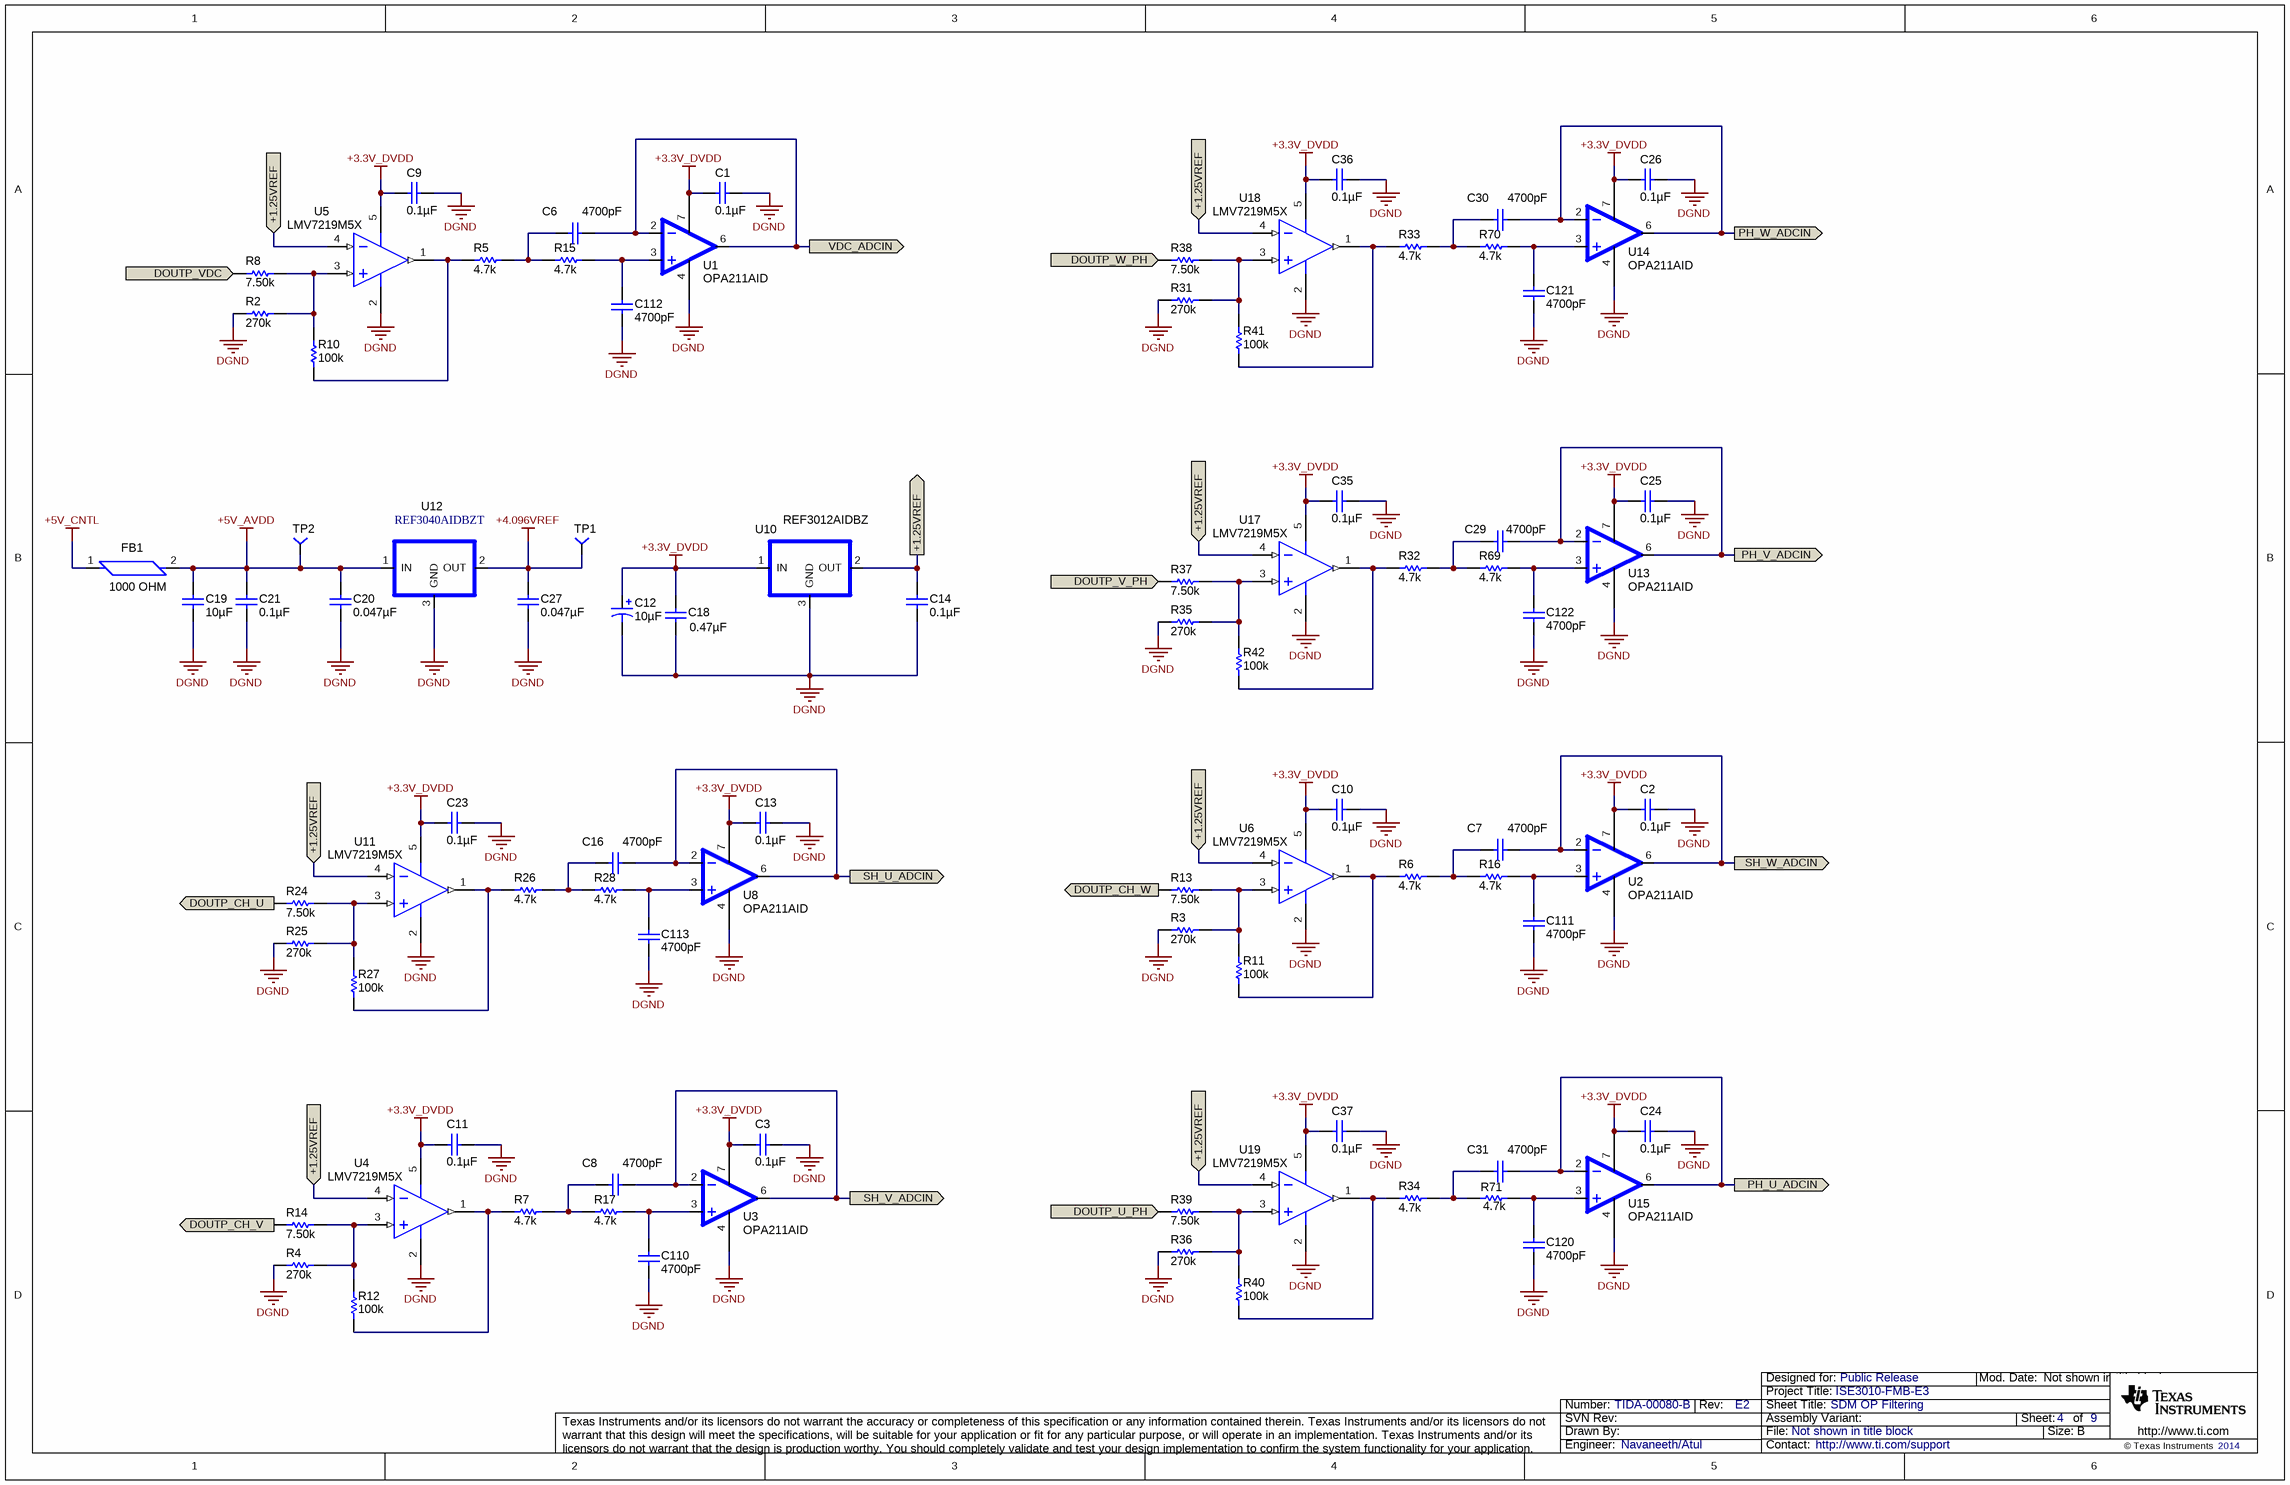
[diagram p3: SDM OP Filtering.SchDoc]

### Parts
C1  ValueDisplayed: 0.1µF  [0603]
C2  ValueDisplayed: 0.1µF  [0603]
C3  ValueDisplayed: 0.1µF  [0603]
C6  ValueDisplayed: 4700pF  [0603]
C7  ValueDisplayed: 4700pF  [0603]
C8  ValueDisplayed: 4700pF  [0603]
C9  ValueDisplayed: 0.1µF  [0603]
C10  ValueDisplayed: 0.1µF  [0603]
C11  ValueDisplayed: 0.1µF  [0603]
C12  ValueDisplayed: 10µF  [SM_RADIAL_B]  (hidden comment: EEE-FC1C100R)
C13  ValueDisplayed: 0.1µF  [0603]
C14  ValueDisplayed: 0.1µF  [0603]  (hidden comment: 06033C104JAT2A)
C16  ValueDisplayed: 4700pF  [0603]
C18  ValueDisplayed: 0.47µF  [0805_HV]  (hidden comment: 0805YC474KAT2A)
C19  ValueDisplayed: 10µF  [1210]
C20  ValueDisplayed: 0.047µF  [0603]
C21  ValueDisplayed: 0.1µF  [0603]
C23  ValueDisplayed: 0.1µF  [0603]
C24  ValueDisplayed: 0.1µF  [0603]
C25  ValueDisplayed: 0.1µF  [0603]
C26  ValueDisplayed: 0.1µF  [0603]
C27  ValueDisplayed: 0.047µF  [0603]
C29  ValueDisplayed: 4700pF  [0603]
C30  ValueDisplayed: 4700pF  [0603]
C31  ValueDisplayed: 4700pF  [0603]
C35  ValueDisplayed: 0.1µF  [0603]
C36  ValueDisplayed: 0.1µF  [0603]
C37  ValueDisplayed: 0.1µF  [0603]
C110  ValueDisplayed: 4700pF  [0603]
C111  ValueDisplayed: 4700pF  [0603]
C112  ValueDisplayed: 4700pF  [0603]
C113  ValueDisplayed: 4700pF  [0603]
C120  ValueDisplayed: 4700pF  [0603]
C121  ValueDisplayed: 4700pF  [0603]
C122  ValueDisplayed: 4700pF  [0603]
FB1  value 1000 OHM  [FB0603]
R2  value 270k  [0603]  (hidden comment: RC0603FR-07270KL)
R3  value 270k  [0603]  (hidden comment: RC0603FR-07270KL)
R4  value 270k  [0603]  (hidden comment: RC0603FR-07270KL)
R5  value 4.7k  [0603]
R6  value 4.7k  [0603]
R7  value 4.7k  [0603]
R8  value 7.50k  [0603]  (hidden comment: CRCW06037K50FKEA)
R10  value 100k  [0603]  (hidden comment: CRCW0603100KFKEA)
R11  value 100k  [0603]  (hidden comment: CRCW0603100KFKEA)
R12  value 100k  [0603]  (hidden comment: CRCW0603100KFKEA)
R13  value 7.50k  [0603]  (hidden comment: CRCW06037K50FKEA)
R14  value 7.50k  [0603]  (hidden comment: CRCW06037K50FKEA)
R15  value 4.7k  [0603]
R16  value 4.7k  [0603]
R17  value 4.7k  [0603]
R24  value 7.50k  [0603]  (hidden comment: CRCW06037K50FKEA)
R25  value 270k  [0603]  (hidden comment: RC0603FR-07270KL)
R26  value 4.7k  [0603]
R27  value 100k  [0603]  (hidden comment: CRCW0603100KFKEA)
R28  value 4.7k  [0603]
R31  value 270k  [0603]  (hidden comment: RC0603FR-07270KL)
R32  value 4.7k  [0603]
R33  value 4.7k  [0603]
R34  value 4.7k  [0603]
R35  value 270k  [0603]  (hidden comment: RC0603FR-07270KL)
R36  value 270k  [0603]  (hidden comment: RC0603FR-07270KL)
R37  value 7.50k  [0603]  (hidden comment: CRCW06037K50FKEA)
R38  value 7.50k  [0603]  (hidden comment: CRCW06037K50FKEA)
R39  value 7.50k  [0603]  (hidden comment: CRCW06037K50FKEA)
R40  value 100k  [0603]  (hidden comment: CRCW0603100KFKEA)
R41  value 100k  [0603]  (hidden comment: CRCW0603100KFKEA)
R42  value 100k  [0603]  (hidden comment: CRCW0603100KFKEA)
R69  value 4.7k  [0603]
R70  value 4.7k  [0603]
R71  value 4.7k  [0603]
TP1  (no value)  [TP-040_RND]
TP2  (no value)  [TP-040_RND]
U1  OPA211AID  [SO8]
U2  OPA211AID  [SO8]
U3  OPA211AID  [SO8]
U4  LMV7219M5X  [MF05A_N]
U5  LMV7219M5X  [MF05A_N]
U6  LMV7219M5X  [MF05A_N]
U8  OPA211AID  [SO8]
U10  REF3012AIDBZ  [SOT-23]
U11  LMV7219M5X  [MF05A_N]
U12  value REF3040AIDBZT  [SOT-23]
U13  OPA211AID  [SO8]
U14  OPA211AID  [SO8]
U15  OPA211AID  [SO8]
U17  LMV7219M5X  [MF05A_N]
U18  LMV7219M5X  [MF05A_N]
U19  LMV7219M5X  [MF05A_N]

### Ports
+1.25VREF, +1.25VREF (out), DOUTP_CH_U (in), DOUTP_CH_V (in), DOUTP_CH_W (in), DOUTP_U_PH (in), DOUTP_V_PH (in), DOUTP_VDC (in), DOUTP_W_PH (in), PH_U_ADCIN, PH_V_ADCIN, PH_W_ADCIN, SH_U_ADCIN, SH_V_ADCIN, SH_W_ADCIN, VDC_ADCIN

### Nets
+3.3V_DVDD: C1.2 C2.2 C3.2 C9.2 C10.2 C11.2 C12.1(+) C13.2 C18.1 C23.2 C24.2 C25.2 C26.2 C35.2 C36.2 C37.2 U1.7(V+) U2.7(V+) U3.7(V+) U4.5(V+) U5.5(V+) U6.5(V+) U8.7(V+) U10.1(IN) U11.5(V+) U13.7(V+) U14.7(V+) U15.7(V+) U17.5(V+) U18.5(V+) U19.5(V+)
+4.096VREF: C27.1 TP1.1 U12.2(OUT)
+5V_AVDD: C19.1 C20.1 C21.2 FB1.2 TP2.1 U12.1(IN)
+5V_CNTL: FB1.1
DGND: C1.1 C2.1 C3.1 C9.1 C10.1 C11.1 C12.2(-) C13.1 C14.2 C18.2 C19.2 C20.2 C21.1 C23.1 C24.1 C25.1 C26.1 C27.2 C35.1 C36.1 C37.1 C110.1 C111.1 C112.1 C113.1 C120.1 C121.1 C122.1 R2.2 R3.2 R4.2 R25.2 R31.2 R35.2 R36.2 U1.4(V-) U2.4(V-) U3.4(V-) U4.2(V-) U5.2(V-) U6.2(V-) U8.4(V-) U10.3(GND) U11.2(V-) U12.3(GND) U13.4(V-) U14.4(V-) U15.4(V-) U17.2(V-) U18.2(V-) U19.2(V-)
+1.25VREF: C14.1 U4.4(IN-) U5.4(IN-) U6.4(IN-) U10.2(OUT) U11.4(IN-) U17.4(IN-) U18.4(IN-) U19.4(IN-) ; port +1.25VREF
DOUTP_CH_U: R24.2 ; port DOUTP_CH_U
DOUTP_CH_V: R14.2 ; port DOUTP_CH_V
DOUTP_CH_W: R13.2 ; port DOUTP_CH_W
DOUTP_U_PH: R39.2 ; port DOUTP_U_PH
DOUTP_V_PH: R37.2 ; port DOUTP_V_PH
DOUTP_VDC: R8.2 ; port DOUTP_VDC
DOUTP_W_PH: R38.2 ; port DOUTP_W_PH
PH_U_ADCIN: C31.2 U15.2 U15.6(OUT) ; port PH_U_ADCIN
PH_V_ADCIN: C29.2 U13.2 U13.6(OUT) ; port PH_V_ADCIN
PH_W_ADCIN: C30.2 U14.2 U14.6(OUT) ; port PH_W_ADCIN
SH_U_ADCIN: C16.2 U8.2 U8.6(OUT) ; port SH_U_ADCIN
SH_V_ADCIN: C8.2 U3.2 U3.6(OUT) ; port SH_V_ADCIN
SH_W_ADCIN: C7.2 U2.2 U2.6(OUT) ; port SH_W_ADCIN
VDC_ADCIN: C6.2 U1.2 U1.6(OUT) ; port VDC_ADCIN
NetC6_1: C6.1 R5.1 R15.2
NetC7_1: C7.1 R6.1 R16.2
NetC8_1: C8.1 R7.1 R17.2
NetC16_1: C16.1 R26.1 R28.2
NetC29_1: C29.1 R32.1 R69.2
NetC30_1: C30.1 R33.1 R70.2
NetC31_1: C31.1 R34.1 R71.2
NetC110_2: C110.2 R17.1 U3.3
NetC111_2: C111.2 R16.1 U2.3
NetC112_2: C112.2 R15.1 U1.3
NetC113_2: C113.2 R28.1 U8.3
NetC120_2: C120.2 R71.1 U15.3
NetC121_2: C121.2 R70.1 U14.3
NetC122_2: C122.2 R69.1 U13.3
NetR2_1: R2.1 R8.1 R10.1 U5.3(IN+)
NetR3_1: R3.1 R11.1 R13.1 U6.3(IN+)
NetR4_1: R4.1 R12.1 R14.1 U4.3(IN+)
NetR5_2: R5.2 R10.2 U5.1(OUT)
NetR6_2: R6.2 R11.2 U6.1(OUT)
NetR7_2: R7.2 R12.2 U4.1(OUT)
NetR24_1: R24.1 R25.1 R27.1 U11.3(IN+)
NetR26_2: R26.2 R27.2 U11.1(OUT)
NetR31_1: R31.1 R38.1 R41.1 U18.3(IN+)
NetR32_2: R32.2 R42.2 U17.1(OUT)
NetR33_2: R33.2 R41.2 U18.1(OUT)
NetR34_2: R34.2 R40.2 U19.1(OUT)
NetR35_1: R35.1 R37.1 R42.1 U17.3(IN+)
NetR36_1: R36.1 R39.1 R40.1 U19.3(IN+)

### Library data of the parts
C1-C3 C9-C11 C13 C21 C23-C26 C35-C37 = C0603C104K5RACTU: as C67 on sheet Power Supply
C6-C8 C16 C29-C31 C110-C113 C120-C122 = 06031C472KAT2A: CAP, CERM, 4700pF, 100V, +/-10%, X7R, 0603; Manufacturer: AVX; Polarized: N; CompType: Capacitor; U/M: EA; Cap_F: 0.0000000047; Tolerance_%: 10; ESR_Ohm: 0.136; Value1: 0.136 ohm; VDC_V: 100; TaMin_C: -55; TaMax_C: 125
C12 = EEE-FC1C100R: CAP, AL, 10uF, 16V, +/-20%, 3 ohm, SMD; Manufacturer: Panasonic; Polarized: Y; CompType: Capacitor; U/M: EA; Cap_F: 0.00001; Tolerance_%: 20; Value1: 3 ohm; VDC_V: 16; ESR_Ohm: 3; IRMS_A: 0.05; TaMin_C: -40; TaMax_C: 105; Cap_Case: B
C14 = 06033C104JAT2A: CAP, CERM, 0.1uF, 25V, +/-5%, X7R, 0603; Manufacturer: AVX; Polarized: N; CompType: Capacitor; U/M: EA; Cap_F: 0.0000001; Tolerance_%: 5; ESR_Ohm: 0.05; Value1: 0.05 ohm; VDC_V: 25; TaMin_C: -55; TaMax_C: 125
C18 = 0805YC474KAT2A: CAP, CERM, 0.47uF, 16V, +/-10%, X7R, 0805; Manufacturer: AVX; Polarized: N; CompType: Capacitor; U/M: EA; Cap_F: 0.00000047; Tolerance_%: 10; ESR_Ohm: 0.011; Value1: 0.011 ohm; VDC_V: 16; TaMin_C: -55; TaMax_C: 125; Cap_Case: 0805
C19 = GMK325AB7106MM-T: as C149 on sheet Power Supply
C20 C27 = 06033C473JAT2A: CAP, CERM, 0.047uF, 25V, +/-5%, X7R, 0603; Manufacturer: AVX; Polarized: N; CompType: Capacitor; U/M: EA; Cap_F: 0.000000047; Tolerance_%: 5; ESR_Ohm: 0.052; Value1: 0.052 ohm; VDC_V: 25; TaMin_C: -55; TaMax_C: 125
FB1 = MMZ1608B102C: as FB4 on sheet Power Supply
R2-R4 R25 R31 R35 R36 = RC0603FR-07270KL: RES, 270k ohm, 1%, 0.1W, 0603; Manufacturer: Yageo America; CompType: Resistor; Res_ohm: 270000; Tolerance_%: 1; Power_W: 0.1; VDC_V: 150; TempCo: 200 ppm/C; U/M: EA
R5-R7 R15-R17 R26 R28 R32-R34 R69-R71 = CRCW06034K70JNEA: RES, 4.7k ohm, 5%, 0.1W, 0603; Manufacturer: Vishay-Dale; CompType: Resistor; Res_ohm: 4700; Value_Code: 4k70; Tolerance_%: 5; Power_W: 0.1; VDC_V: 75; TempCo: 200 ppm/C; EIA_Code: E24; U/M: EA
R8 R13 R14 R24 R37-R39 = CRCW06037K50FKEA: RES, 7.50k ohm, 1%, 0.1W, 0603; Manufacturer: Vishay-Dale; CompType: Resistor; Res_ohm: 7500; Value_Code: 7k50; Tolerance_%: 1; Power_W: 0.1; VDC_V: 75; TempCo: 100 ppm/C; EIA_Code: E96; U/M: EA
R10-R12 R27 R40-R42 = CRCW0603100KFKEA: RES, 100k ohm, 1%, 0.1W, 0603; Manufacturer: Vishay-Dale; CompType: Resistor; Res_ohm: 100000; Tolerance_%: 1; Power_W: 0.1; VDC_V: 75; TempCo: 100 ppm/C; EIA_Code: E96; U/M: EA
TP1 TP2 = TP-040_RND: Test Point, O.040 Hole; Manufacturer: STD; Value: STD
U1-U3 U8 U13-U15 = OPA211AID: IC, 1.1nV/vHz Noise, Low Power, Precision OpAmp; Manufacturer: TI; Alternate Manufacturer: None; Area: 75900
U4-U6 U11 U17-U19 = LMV7219M5X: 7 nsec, 2.7V to 5V Comparator with Rail-to- Rail Output, 5-pin SOT-23; Manufacturer: National Semiconductor; PackageTopMarking: C14A*XTT; PowerWise: Y
U10 = REF30XXAIDBZ: IC, Voltage Reference, 50ppm/°C Max, 50uA; Manufacturer: TI; Alternate Manufacturer: None; Area: 16384
U12 = REF30XXAIDBZ: Voltage Reference, SRS PREC 4.096V SOT23-3; Manufacturer: TI; Alternate Manufacturer: None; Area: 16384; Description: IC, Voltage Reference, 50ppm/°C Max, 50uA

## Sheet Control card connector.SchDoc: Control card connector
size 431 x 279 mm; Date: Not shown in title block; ApprovedBy: Not shown in title block; CheckedBy: Not shown in title block; Author: Not shown in title block; CompanyName: Not shown in title block; Engineer: Not shown in title block; Organization: Not shown in title block; Address1: Not shown in title block; Address2: Not shown in title block; Address3: Not shown in title block; Address4: Not shown in title block; DocumentNumber: 5; Revision: Use project parameter SCH_Rev; SheetNumber: 5; SheetTotal: 9; PageSetup: Record=PageOptions|CenterHorizontal=True|CenterVertical=True|PrintScale=1.00|XCorrection=1.00|YCorrection=1.00|PrintKind=0|BorderSize=5000000|LeftOffset=0|BottomOffset=0|Orientation=2|PaperLength=1000|PaperWidth=1000|Scale=100|PaperSource=15|PrintQuality=600|MediaType=1|DitherType=10|PaperKind=Letter|PrintScaleMode=1
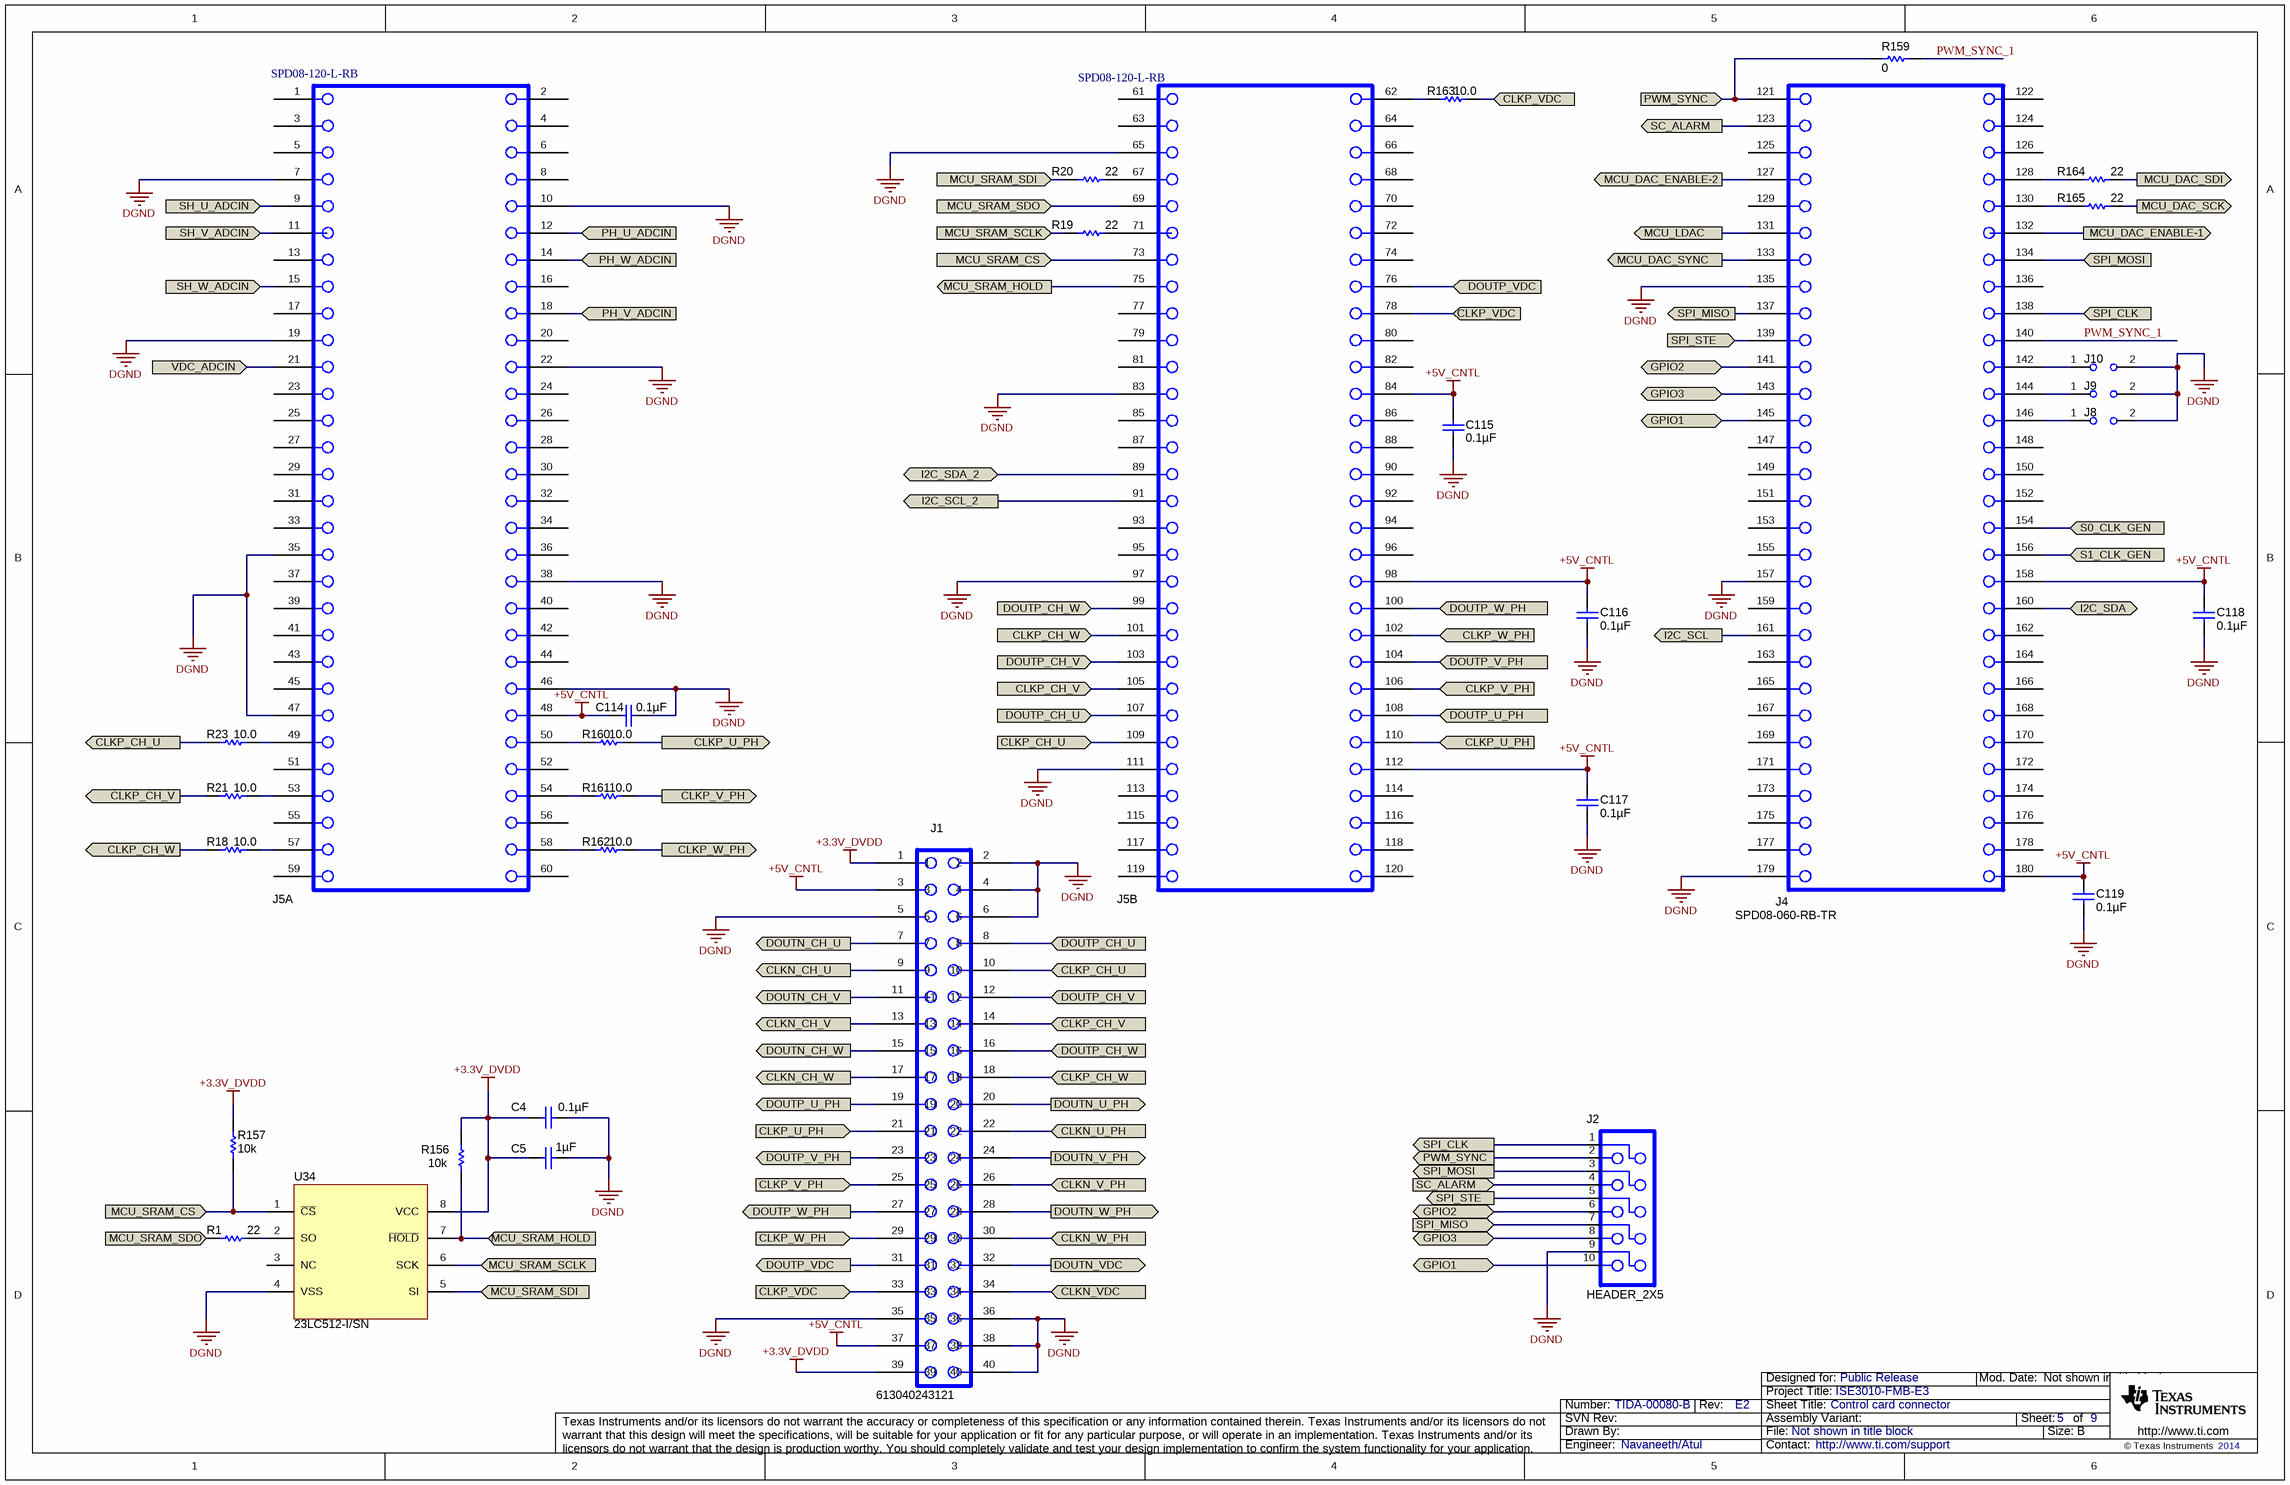
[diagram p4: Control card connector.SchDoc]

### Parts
C4  ValueDisplayed: 0.1µF  [0603]  (hidden comment: 0603YC104JAT2A)
C5  ValueDisplayed: 1µF  [0603]  (hidden comment: C1608X5R1C105K)
C114  ValueDisplayed: 0.1µF  [0603]
C115  ValueDisplayed: 0.1µF  [0603]
C116  ValueDisplayed: 0.1µF  [0603]
C117  ValueDisplayed: 0.1µF  [0603]
C118  ValueDisplayed: 0.1µF  [0603]
C119  ValueDisplayed: 0.1µF  [0603]
J1  613040243121  [CONN_613040243121]
J2  HEADER_2X5  [HEADER_2X5]
J4  SPD08-060-RB-TR  [HSEC8-130-01-L-DV-A]
J5  SPD08-120-L-RB  [HSEC8-160-01-L-DV-A-L]  (parts A,B of 2)
J8  (no value)  [HDR100_1X2]
J9  (no value)  [HDR100_1X2]
J10  (no value)  [HDR100_1X2]
R1  value 22  [0402]  (hidden comment: CRCW040222R0JNED)
R18  value 10.0  [0603]
R19  value 22  [0402]  (hidden comment: CRCW040222R0JNED)
R20  value 22  [0402]  (hidden comment: CRCW040222R0JNED)
R21  value 10.0  [0603]
R23  value 10.0  [0603]
R156  value 10k  [0603]  (hidden comment: CRCW060310K0JNEA)
R157  value 10k  [0603]  (hidden comment: CRCW060310K0JNEA)
R159  value 0  [0603]  (hidden comment: CRCW06030000Z0EA)
R160  value 10.0  [0603]
R161  value 10.0  [0603]
R162  value 10.0  [0603]
R163  value 10.0  [0603]
R164  value 22  [0402]  (hidden comment: CRCW040222R0JNED)
R165  value 22  [0402]  (hidden comment: CRCW040222R0JNED)
U34  23LC512-I/SN  [SO8]

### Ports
CLKN_CH_U, CLKN_CH_V, CLKN_CH_W, CLKN_U_PH (in), CLKN_V_PH (in), CLKN_VDC (in), CLKN_W_PH (in), CLKP_CH_U, CLKP_CH_U (in), CLKP_CH_U (out), CLKP_CH_V, CLKP_CH_V (in), CLKP_CH_V (out), CLKP_CH_W, CLKP_CH_W (in), CLKP_CH_W (out), CLKP_U_PH (in), CLKP_U_PH (out), CLKP_V_PH (in), CLKP_V_PH (out), CLKP_VDC (in), CLKP_W_PH (in), CLKP_W_PH (out), DOUTN_CH_U, DOUTN_CH_V, DOUTN_CH_W, DOUTN_U_PH (out), DOUTN_V_PH (out), DOUTN_VDC (out), DOUTN_W_PH (out), DOUTP_CH_U, DOUTP_CH_V, DOUTP_CH_W, DOUTP_U_PH, DOUTP_U_PH (out), DOUTP_V_PH, DOUTP_V_PH (out), DOUTP_VDC (in), DOUTP_VDC (out), DOUTP_W_PH, DOUTP_W_PH (out), GPIO1 (bidir), GPIO2 (bidir), GPIO3 (bidir), I2C_SCL, I2C_SCL_2 (out), I2C_SDA (bidir), I2C_SDA_2 (bidir), MCU_DAC_ENABLE-1 (out), MCU_DAC_ENABLE-2, MCU_DAC_SCK (out), MCU_DAC_SDI (out), MCU_DAC_SYNC, MCU_LDAC, MCU_SRAM_CS (in), MCU_SRAM_HOLD (in), MCU_SRAM_HOLD (out), MCU_SRAM_SCLK (in), MCU_SRAM_SDI (in), MCU_SRAM_SDO (in), MCU_SRAM_SDO (out), PH_U_ADCIN (in), PH_V_ADCIN (in), PH_W_ADCIN (in), PWM_SYNC, PWM_SYNC (in), S0_CLK_GEN, S1_CLK_GEN, SC_ALARM (in), SC_ALARM (out), SH_U_ADCIN, SH_V_ADCIN, SH_W_ADCIN, SPI_CLK, SPI_CLK (in), SPI_MISO, SPI_MISO (in), SPI_MOSI, SPI_MOSI (in), SPI_STE, SPI_STE (in), VDC_ADCIN

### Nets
+3.3V_DVDD: C4.1 C5.1 J1.1 J1.39 R156.2 R157.2 U34.8(VCC)
+5V_CNTL: C114.2 C115.2 C116.2 C117.2 C118.2 C119.2 J1.3 J1.37 J4.158 J4.180 J5.48 J5.84 J5.98 J5.112
DGND: C4.2 C5.2 C114.1 C115.1 C116.1 C117.1 C118.1 C119.1 J1.2 J1.4 J1.5 J1.6 J1.35 J1.36 J1.38 J1.40 J2.9(P9) J4.135 J4.157 J4.179 J5.7 J5.10 J5.19 J5.22 J5.35 J5.38 J5.46 J5.47 J5.65 J5.83 J5.97 J5.111 J8.2 J9.2 J10.2 U34.4(VSS)
CLKN_CH_U: J1.9 ; port CLKN_CH_U
CLKN_CH_V: J1.13 ; port CLKN_CH_V
CLKN_CH_W: J1.17 ; port CLKN_CH_W
CLKN_U_PH: J1.22 ; port CLKN_U_PH
CLKN_V_PH: J1.26 ; port CLKN_V_PH
CLKN_VDC: J1.34 ; port CLKN_VDC
CLKN_W_PH: J1.30 ; port CLKN_W_PH
CLKP_CH_U: J1.10 J5.109 R23.1 ; port CLKP_CH_U
CLKP_CH_V: J1.14 J5.105 R21.1 ; port CLKP_CH_V
CLKP_CH_W: J1.18 J5.101 R18.1 ; port CLKP_CH_W
CLKP_U_PH: J1.21 J5.110 R160.2 ; port CLKP_U_PH
CLKP_V_PH: J1.25 J5.106 R161.2 ; port CLKP_V_PH
CLKP_VDC: J1.33 J5.78 R163.2 ; port CLKP_VDC
CLKP_W_PH: J1.29 J5.102 R162.2 ; port CLKP_W_PH
DOUTN_CH_U: J1.7 ; port DOUTN_CH_U
DOUTN_CH_V: J1.11 ; port DOUTN_CH_V
DOUTN_CH_W: J1.15 ; port DOUTN_CH_W
DOUTN_U_PH: J1.20 ; port DOUTN_U_PH
DOUTN_V_PH: J1.24 ; port DOUTN_V_PH
DOUTN_VDC: J1.32 ; port DOUTN_VDC
DOUTN_W_PH: J1.28 ; port DOUTN_W_PH
DOUTP_CH_U: J1.8 J5.107 ; port DOUTP_CH_U
DOUTP_CH_V: J1.12 J5.103 ; port DOUTP_CH_V
DOUTP_CH_W: J1.16 J5.99 ; port DOUTP_CH_W
DOUTP_U_PH: J1.19 J5.108 ; port DOUTP_U_PH
DOUTP_V_PH: J1.23 J5.104 ; port DOUTP_V_PH
DOUTP_VDC: J1.31 J5.76 ; port DOUTP_VDC
DOUTP_W_PH: J1.27 J5.100 ; port DOUTP_W_PH
GPIO1: J2.10(P10) J4.145 ; port GPIO1
GPIO2: J2.6(P6) J4.141 ; port GPIO2
GPIO3: J2.8(P8) J4.143 ; port GPIO3
I2C_SCL: J4.161 ; port I2C_SCL
I2C_SCL_2: J5.91 ; port I2C_SCL_2
I2C_SDA: J4.160 ; port I2C_SDA
I2C_SDA_2: J5.89 ; port I2C_SDA_2
MCU_DAC_ENABLE-1: J4.132 ; port MCU_DAC_ENABLE-1
MCU_DAC_ENABLE-2: J4.127 ; port MCU_DAC_ENABLE-2
MCU_DAC_SCK: R165.1 ; port MCU_DAC_SCK
MCU_DAC_SDI: R164.1 ; port MCU_DAC_SDI
MCU_DAC_SYNC: J4.133 ; port MCU_DAC_SYNC
MCU_LDAC: J4.131 ; port MCU_LDAC
MCU_SRAM_CS: J5.73 R157.1 U34.1(~{CS}) ; port MCU_SRAM_CS
MCU_SRAM_HOLD: J5.75 R156.1 U34.7(~{HOLD}) ; port MCU_SRAM_HOLD
MCU_SRAM_SCLK: R19.2 U34.6(SCK) ; port MCU_SRAM_SCLK
MCU_SRAM_SDI: R20.2 U34.5(SI) ; port MCU_SRAM_SDI
MCU_SRAM_SDO: J5.69 R1.2 ; port MCU_SRAM_SDO
PH_U_ADCIN: J5.12 ; port PH_U_ADCIN
PH_V_ADCIN: J5.18 ; port PH_V_ADCIN
PH_W_ADCIN: J5.14 ; port PH_W_ADCIN
PWM_SYNC: J2.2(P2) J4.121 R159.1 ; port PWM_SYNC
PWM_SYNC_1: J4.140 R159.2
S0_CLK_GEN: J4.154 ; port S0_CLK_GEN
S1_CLK_GEN: J4.156 ; port S1_CLK_GEN
SC_ALARM: J2.4(P4) J4.123 ; port SC_ALARM
SH_U_ADCIN: J5.9 ; port SH_U_ADCIN
SH_V_ADCIN: J5.11 ; port SH_V_ADCIN
SH_W_ADCIN: J5.15 ; port SH_W_ADCIN
SPI_CLK: J2.1(P1) J4.138 ; port SPI_CLK
SPI_MISO: J2.7(P7) J4.137 ; port SPI_MISO
SPI_MOSI: J2.3(P3) J4.134 ; port SPI_MOSI
SPI_STE: J2.5(P5) J4.139 ; port SPI_STE
VDC_ADCIN: J5.21 ; port VDC_ADCIN
NetJ4_128: J4.128 R164.2
NetJ4_130: J4.130 R165.2
NetJ4_142: J4.142 J10.1
NetJ4_144: J4.144 J9.1
NetJ4_146: J4.146 J8.1
NetJ5_49: J5.49 R23.2
NetJ5_50: J5.50 R160.1
NetJ5_53: J5.53 R21.2
NetJ5_54: J5.54 R161.1
NetJ5_57: J5.57 R18.2
NetJ5_58: J5.58 R162.1
NetJ5_62: J5.62 R163.1
NetJ5_67: J5.67 R20.1
NetJ5_71: J5.71 R19.1
NetR1_1: R1.1 U34.2(SO)

Not connected (* = marked no-connect by the designer): J4 122 124 125 126 129 136 147 148 149 150 151 152 153 155 159 162 163 164 165 166 167 168 169 170 171 172 173 174 175 176 177 178; J5 1 2 3 4 5 6 8 13 16 17 20 23 24 25 26 27 28 29 30 31 32 33 34 36 37 39 40 41 42 43 44 45 51 52 55 56 59 60 61 63 64 66 68 70 72 74 77 79 80 81 82 85 86 87 88 90 92 93 94 95 96 113 114 115 116 117 118 119 120; U34 3(NC)

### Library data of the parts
C4 = 0603YC104JAT2A: as C139 on sheet Power Supply
C5 = C1608X5R1C105K: CAP, CERM, 1uF, 16V, +/-10%, X5R, 0603; Manufacturer: TDK; Polarized: N; CompType: Capacitor; U/M: EA; Cap_F: 0.000001; Tolerance_%: 10; ESR_Ohm: 0.0057; Value1: 0.0057 ohm; VDC_V: 16; TaMin_C: -55; TaMax_C: 85
C114-C119 = C0603C104K5RACTU: as C67 on sheet Power Supply
J1 = CONN_613040243121: Connector, Right Angle, Male, 2x20 pin, 100mil spacing; Manufacturer: WURTH ELEKTRONIK; area: 1.262.250
J2 = HEADER_2X5: Header, Male 2x5-pin, 100mil spacing; Manufacturer: Sullins; PartNumber: PEC05DAAN; area: 100000; Value: PEC05DAAN
J4 = HSEC8-130-01-L-DV-A: CONN HIGH SPD CARD EDGE 60 POS; Manufacturer: 3M; SymbolCreator: x0120606; CompType: Edge Rate Card Socket
J5 = HSEC8-160-01-L-DV-A-L: CONN HIGH SPD CARD EDGE 120 POS; Manufacturer: 3M
J8-J10 = JUMPER_2X100MIL: Header, Male 2-pin, 100mil spacing,; Manufacturer: Sullins; PartNumber: PEC02SAAN; area: 20000; Value: PEC02SAAN
R1 R19 R20 R164 R165 = CRCW040222R0JNED: RES, 22 ohm, 5%, 0.063W, 0402; Manufacturer: Vishay-Dale; CompType: Resistor; Value_Code: 22R0; Tolerance_%: 5; Power_W: 0.063; VDC_V: 50; TempCo: 200 ppm/C; EIA_Code: E24; U/M: EA
R18 R21 R23 R160-R163 = CRCW060310R0FKEA: RES, 10.0 ohm, 1%, 0.1W, 0603; Manufacturer: Vishay-Dale; CompType: Resistor; Res_ohm: 10; Value_Code: 10R0; Tolerance_%: 1; Power_W: 0.1; VDC_V: 75; TempCo: 100 ppm/C; EIA_Code: E96; U/M: EA
R156 R157 = CRCW060310K0JNEA: RES, 10k ohm, 5%, 0.1W, 0603; Manufacturer: Vishay-Dale; CompType: Resistor; Res_ohm: 10000; Value_Code: 10k0; Tolerance_%: 5; Power_W: 0.1; VDC_V: 75; TempCo: 200 ppm/C; EIA_Code: E24; U/M: EA
R159 = CRCW06030000Z0EA: as R139 on sheet Power Supply
U34 = 23LC512-I/SN: IC SRAM 512KBIT 20MHZ 8SOIC; Alternate Manufacturer: None; Manufacturer: Microchip Technology; SymbolCreator: x0120606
